(* Logix 5000 project; controller MyControlLogix vendor 1 type 14 code 51 rev 16.20; software revision 16.04 *)

TASK MainTask (continuous, watchdog 500 ms) : MainProgram

MODULES
   Local : vendor 1 type 14 code 51 (ICP 0, rev 16.20)
      AFC : vendor 1 type 0 code 15 (ICP 1, rev 1.1, Output RPI 5 ms)
END_MODULES

TYPE AFC :   // Main user defined data type
STRUCT
   Meters : AFC_Meters[16];   // Stores meter process variables, results, analysis (gas) and module profile
   MeterSignals : AFC_Meter_Reset;   // Sets meter signals (write archive, reset accumulator and select stream)
   ModbusGateway : AFC_Modbus;   // Reads and write data between processor and module modbus table
   ModbusMaster : AFC_ModbusMaster;   // Setup modbus master commands to be sent to remote slaves (through Port 3)
   ModbusPassThru : AFC_ModbusPassThru;   // Modbus pass-thru data
   Prove : AFC_Prove;   // Proving implementation (only firmware 2.07.000 or later)
   Flags : AFC_Flag;   // Wallclock update commands
   EnableMeter : AFC_Meter;   // Enable meters (this action can also be performed through AFC Manager)
   DisableMeter : AFC_Meter;   // Disable meters (this action can also be performed through AFC Manager)
   EnableStatus : AFC_Meter;   // Meter current status (0=disabled, 1=enabled)
   Site_Status : AFC_Site_Status;   // Site status
   Site_Alarms : AFC_Site_Alarms;   // Site Alarms
   CycleCounter : INT;   // Reflects current block ID calculated by ladder to be sent to the module
   inputbuffer : INT[250];   // Input buffer contains the complete block to be copied from the module
   outputbuffer : INT[248];   // Output buffer contains data the complete block to be copied to the module
   clockstructure : AFC_Time;   // Stores clock information
   Util : AFC_Util;   // Convenience variables used by ladder logic
END_STRUCT
END_TYPE

TYPE AFC_Analysis_High :   // High precision (floating point) Gas Analysis support. This feature is only supported for firmware version 2.07.000 or later
STRUCT
   EnableOnce : BOOL;   // Set to ON to request the high precision analysis update one time. It automatically resets to 0 after the request.
   Stream : INT;   // Stream number. Range is 0 (active) and 1 to 4.
   Components : AFC_Components_High;   // AFC High Precision Molar Analysis (floating point)
END_STRUCT
END_TYPE

TYPE AFC_Analysis_Low :   // Low precision (16-bit word) Gas Analysis support.
STRUCT
   EnableContinuous : BOOL;   // Set to ON to update the low precision molar analysis. The data will be updated continuously while the molar analysis is updated.
   Stream : INT;   // Select stream for molar analysis (low precision) update. Valid range is 0 (active) and 1 to 4.
   Components : AFC_Components_Low;   // Gas components in low precision format (16-bit word)
END_STRUCT
END_TYPE

TYPE AFC_Analysis_Status :   // Contains stream configuration information concerning high/low precision.
STRUCT
   Update : BOOL;   // Trigger update of analysis status
   Stream_Precision : SINT[4];   // Stream Precision ( 1 = Low, 2 = High)
   Slot_In_Stream : SINT[4];   // Slot number associated to each stream (0-BASED) Ex: (Slot_In_Stream[0] = 1 means stream 1 is set for slot 2)
   Slot_Precision : SINT[4];   // Precision of each slot (0-BASED) (2=high precision/first slot, 1=low precision,0=high precision/second slot)
END_STRUCT
END_TYPE

TYPE AFC_Components_High :   // High precision gas component analysis (only supported version 2.07.000)
STRUCT
   C1 : REAL;   // Methane
   N2 : REAL;   // Nitrogen
   CO2 : REAL;   // Carbon Dioxide
   C2 : REAL;   // Ethane
   C3 : REAL;   // Propane
   H20 : REAL;   // Water
   H2S : REAL;   // Hydrogen Sulphide
   H2 : REAL;   // Hydrogen
   CO : REAL;   // Carbon Monoxide
   O2 : REAL;   // Oxygen
   IC4 : REAL;   // Iso-butane
   NC4 : REAL;   // Normal Butane
   IC5 : REAL;   // Iso-pentane
   NC5 : REAL;   // Normal-pentane
   C6 : REAL;   // Hexane
   C7 : REAL;   // Heptane
   C8 : REAL;   // Octane
   C9 : REAL;   // Nonane
   C10 : REAL;   // Decane
   He : REAL;   // Helium
   Ar : REAL;   // Argon
   NeoC5 : REAL;   // Not Used
   Ux_User1 : REAL;   // Not Used
   Uy_User2 : REAL;   // Not Used
END_STRUCT
END_TYPE

TYPE AFC_Components_Low :   // Low precision gas component analysis
STRUCT
   C1 : INT;   // Methane
   N2 : INT;   // Nitrogen
   CO2 : INT;   // Carbon dioxide
   C2 : INT;   // Ethane
   C3 : INT;   // Propane
   H20 : INT;   // Water
   H2S : INT;   // Hydrogen sulphide
   H2 : INT;   // Hydrogen
   CO : INT;   // Carbon monoxide
   O2 : INT;   // Oxygen
   IC4 : INT;   // Iso-butane
   NC4 : INT;   // Normal butane
   IC5 : INT;   // Iso-pentane
   NC5 : INT;   // Normal pentane
   C6 : INT;   // Hexane
   C7 : INT;   // Heptane
   C8 : INT;   // Octane
   C9 : INT;   // Nonane
   C10 : INT;   // Decane
   He : INT;   // Helium
   Ar : INT;   // Argon
   NeoC5 : INT;   // Not used
   Ux_User1 : INT;   // Not used
   Uy_User2 : INT;   // Not used
END_STRUCT
END_TYPE

TYPE AFC_Flag :   // Flags contains status information updated by ladder and also trigger bits for clock update
STRUCT
   AFC_Stopped : BOOL;   // Indicates that the module has sent a new input block to be processed by ladder - UPDATED BY LADDER
   AFC_InputSequenceNum : INT;   // Meter number (0 -15) associated to blocks 1-16. Used to update "Profile" (meter type and product group.) UPDATED BY LADDER
   AFC_Set_Clock : BOOL;   // Set to 1 to update module wallclock (using processor as a source) UPDATED BY USER
   plc_set_clock : BOOL;   // Set to 1 to set processor wallclock UPDATED BY USER
END_STRUCT
END_TYPE

TYPE AFC_Meter :   // Used for meter enable and disable tags
STRUCT
   Meter1 : BOOL;   // Meter 1
   Meter2 : BOOL;   // Meter 2
   Meter3 : BOOL;   // Meter 3
   Meter4 : BOOL;   // Meter 4
   Meter5 : BOOL;   // Meter 5
   Meter6 : BOOL;   // Meter 6
   Meter7 : BOOL;   // Meter 7
   Meter8 : BOOL;   // Meter 8
   Meter9 : BOOL;   // Meter 9
   Meter10 : BOOL;   // Meter 10
   Meter11 : BOOL;   // Meter 11
   Meter12 : BOOL;   // Meter 12
   Meter13 : BOOL;   // Meter 13
   Meter14 : BOOL;   // Meter 14
   Meter15 : BOOL;   // Meter 15
   Meter16 : BOOL;   // Meter 16
END_STRUCT
END_TYPE

TYPE AFC_Meter_Analysis :   // Meter analysis components. Allows the processor to update molar analysis for low precision and high precision streams.
STRUCT
   Low_Precision : AFC_Analysis_Low;   // Low precision gas components (16-bit word per component)
   High_Precision : AFC_Analysis_High;   // High precision gas components (floating point per component). Only supported for firmware version 2.07.000 or later
   Status : AFC_Analysis_Status;   // Stream analysis status - contains stream and slot configuration data
END_STRUCT
END_TYPE

TYPE AFC_Meter_Differential_Gas_Input :   // Calculation results for differential meter with gas product
STRUCT
   Net_Accumulator : DINT;   // Net accumulator
   Net_Flowrate : REAL;   // Net flow rate
   Gross_Flowrate : REAL;   // Gross flow rate
   Fpv : REAL;   // Super compressibility
   Cprime : REAL;   // Cprime
END_STRUCT
END_TYPE

TYPE AFC_Meter_Differential_Gas_Output :   // Process Variables for differential meter with gas product
STRUCT
   Temperature : REAL;   // Temperature
   Pressure : REAL;   // Static pressure
   Differential_Pressure : REAL;   // Differential pressure if Primary Input = Differential pressure OR Flow Rate if Primary Input = Flow rate
END_STRUCT
END_TYPE

TYPE AFC_Meter_Differential_Liquid_Input :   // Calculation Results for differential meter with lliquid product
STRUCT
   Net_Accumulator : DINT;   // Net accumulator
   Net_Flowrate : REAL;   // Net flow rate
   Gross_Accumulator : DINT;   // Gross acumulator
   Gross_Standard_Accumulator : DINT;   // Gross standard accumulator
   Mass_Accumulator : DINT;   // Mass accumulator
END_STRUCT
END_TYPE

TYPE AFC_Meter_Differential_Liquid_Output :   // Process Variables for differential meter with liquid product
STRUCT
   Water_Percent : INT;   // Water %
   Temperature : REAL;   // Temperature
   Pressure : REAL;   // Static Pressure
   Differential_Pressure : REAL;   // Differential pressure if Primary Input = Differential pressure OR Flow Rate if Primary Input = Flow rate
   Density : REAL;   // Density
END_STRUCT
END_TYPE

TYPE AFC_Meter_Linear_Gas_Input :   // Calculation Results for linear meter with gas product
STRUCT
   Net_Accumulator : DINT;   // Net accumulator
   Net_Flowrate : REAL;   // Net flow rate
   Gross_Flowrate : REAL;   // Gross flow rate
   Fpv : REAL;   // Supercompressibility
   CPrime : REAL;   // CPrime
END_STRUCT
END_TYPE

TYPE AFC_Meter_Linear_Gas_Output :   // Process Variables for linear meter with gas product
STRUCT
   Temperature : REAL;   // Temperature
   Pressure : REAL;   // Pressure
   Meter_Pulses : DINT;   // Pulse count
   Pulse_Frequency : REAL;   // Pulse Frequency (Hz)
END_STRUCT
END_TYPE

TYPE AFC_Meter_Linear_Liquid_Input :   // Calculation Results for linear meter with liquid product
STRUCT
   Net_Accumulator : DINT;   // Net accumulator
   Net_Flowrate : REAL;   // Net flow rate
   Gross_Accumulator : DINT;   // Gross accumulator
   Gross_Standard_Accumulator : DINT;   // Gross standard accumulator
   Mass_Accumulator : DINT;   // Mass accumulator
END_STRUCT
END_TYPE

TYPE AFC_Meter_Linear_Liquid_Output :   // Process Variables for linear meter with liquid product
STRUCT
   Water_Percent : INT;   // Water (%)
   Temperature : REAL;   // Temperature
   Pressure : REAL;   // Pressure
   Meter_Pulses : DINT;   // Meter pulses
   Density : REAL;   // Density
   Pulse_Frequency : REAL;   // Pulse frequency (Hz)
END_STRUCT
END_TYPE

TYPE AFC_Meter_Reset :   // Meter signals to request for reset accumulator, select stream and write archives.
STRUCT
   Enable : BOOL;   // Enable meter signal request. UPDATED BY USER
   BID : INT;   // Block ID for meter signal request. UPDATED BY LOGIC
   Meter : INT;   // Meter number (1-16) associated to signal request UPDATED BY USER
   Action : INT;   // Action word built from Signal bits (UPDATED by USER)
   Signals : AFC_Meter_Signals;   // Signals request bits
   ResetOnce : BOOL;   // Request signal update once
   LastBlockID : INT;   // Last block ID associated to signals request
END_STRUCT
END_TYPE

TYPE AFC_Meter_Results :   // AFC meter results calculated by the module to the processor
STRUCT
   BID : INT;   // Block ID associated to calculation results
   Alarms : INT;   // Meter alarms
   DifferentialGas : AFC_Meter_Differential_Gas_Input;   // Differential meter / product gas
   DifferentialLiquid : AFC_Meter_Differential_Liquid_Input;   // Differential meter / product liquid
   LinearGas : AFC_Meter_Linear_Gas_Input;   // Linear meter / product gas
   LinearLiquid : AFC_Meter_Linear_Liquid_Input;   // Linear meter / product liquid
END_STRUCT
END_TYPE

TYPE AFC_Meter_Signals :   // Meter signals options
STRUCT
   Sel_Stream1 : BOOL;   // Set to 1 to select stream 1
   Sel_Stream2 : BOOL;   // Set to 1 to select stream 2
   Sel_Stream3 : BOOL;   // Set to 1 to select stream 3
   Sel_Stream4 : BOOL;   // Set to 1 to select stream 4
   Res_Acc1 : BOOL;   // Set to 1 to reset resettable accumulator 1
   Res_Acc2 : BOOL;   // Set to 1 to reset resettable accumulator 2
   Res_Acc3 : BOOL;   // Set to 1 to reset resettable accumulator 3
   Res_Acc4 : BOOL;   // Set to 1 to reset resettable accumulator 4
   Wr_Daily_Archive : BOOL;   // Set to 1 to write daily archive
   Wr_Hrly_Archive : BOOL;   // Set to 1 to write hourly archive
END_STRUCT
END_TYPE

TYPE AFC_Meter_Variables :   // Meter process variables from processor to the module.
STRUCT
   BID : INT;   // Block ID associated to meter process variable block (from processor to the module)
   DifferentialGas : AFC_Meter_Differential_Gas_Output;   // Differential meter and gas product
   DifferentialLiquid : AFC_Meter_Differential_Liquid_Output;   // Differential meter and liquid product
   LinearGas : AFC_Meter_Linear_Gas_Output;   // Linear meter and gas product
   LinearLiquid : AFC_Meter_Linear_Liquid_Output;   // Linear meter and liquid product
END_STRUCT
END_TYPE

TYPE AFC_Meters :   // Main meter data structure. Contains process variables, calculation results, gas analysis, profile update
STRUCT
   Variables : AFC_Meter_Variables;   // Input process variables to be transferred to the module
   Results : AFC_Meter_Results;   // Calculation results transferred from the module
   Analysis : AFC_Meter_Analysis;   // Molar Analysis data to be transferred to the module (only for gas products with online gas chromatograph applications)
   Profile : AFC_Status;   // Module profile (meter type/product group) transfered from the module
END_STRUCT
END_TYPE

TYPE AFC_Modbus :   // Modbus Gateway data structure. Select the number of commands to be used (1 to 10). O will disable this funcionality.
STRUCT
   CommandCount : INT;   // Defines the number of Modbus Gateway Blocks to be used (1 to 10). Set to 0 to disable the feature.
   Command : AFC_ModbusGateway[10];   // Modbus gateway commands - contains setup and modbus data
END_STRUCT
END_TYPE

TYPE AFC_ModbusConfig :   // Modbus gateway configuration options
STRUCT
   Enable : BOOL;   // Set to 1 to enable modbus gateway command (0=disable)
   StartRegister : INT;   // Start modbus address
   RegisterCount : INT;   // Word count (200 max)
   FunctionType_Write : BOOL;   // 0 = read command, 1 = write command
   RegisterType_Input : BOOL;   // 0 = holding register, 1 = input register
   SlaveType_Virtual : BOOL;   // 0 = primary slave, 1 = virtual slave
END_STRUCT
END_TYPE

TYPE AFC_ModbusGateway :   // Modbus gateway complete data structure
STRUCT
   Config : AFC_ModbusConfig;   // Config data to be entered by the user.
   BOD : INT;   // Block ID automatically generated by ladder
   WriteData : INT[200];   // Contains modbus data written to the module (write commands)
   BID : INT;   // Block ID automatically generated by ladder
   ReadData : INT[200];   // Contains modbus data read from the module (read commands)
END_STRUCT
END_TYPE

TYPE AFC_ModbusMaster :   // Modbus master operation. Port 3 must be configured as modbus master through AFC Manager to use this feature.
STRUCT
   Enable : BOOL;   // Enable the modbus master funcionality
   CommandIndex : INT;   // Selects which command index will be executed
   Command : AFC_ModbusMasterElement[10];   // Each command contains a specific modbus request to be sent out of the port
END_STRUCT
END_TYPE

TYPE AFC_ModbusMasterConfig :   // Modbus master command settings
STRUCT
   Enable : BOOL;   // Set to 1 to enable command (0=disable)
   FunctionType_Write : BOOL;   // Set to 1 to select write command (0=read command)
   RegisterBank_Input : BOOL;   // Set to 1 to select input register (0=holding register)
   DataType : AFC_ModbusMasterDataType;   // Select data type format
   SwapOption : AFC_ModbusMasterSwap;   // Select byte and word swap (1 = swap, 0 = no swap)
   Type_Swap : INT;   // This value is calculated by ladder logic and must not be modified by user
   SlaveAddress : INT;   // Modbus slave address of remote device
   ModbusAddress : INT;   // Modbus data address on remote slave
   ElementCount : INT;   // Number of data elements (125 words)
END_STRUCT
END_TYPE

TYPE AFC_ModbusMasterDataType :   // Modbus master data type selection
STRUCT
   Bit : BOOL;   // bit type
   Word : BOOL;   // word type (16-bit)
   Long : BOOL;   // long integer (32-bit)
   LongRemote : BOOL;   // long integer (32-bit)
END_STRUCT
END_TYPE

TYPE AFC_ModbusMasterElement :   // Modbus master controller tag. Requires port 3 to be configured as a modbus master device.
STRUCT
   Output : AFC_ModbusMasterOut;   // From processor to the module
   Input : AFC_ModbusMasterIn;   // From module to the processor
END_STRUCT
END_TYPE

TYPE AFC_ModbusMasterIn :   // Modbus master input tag.
STRUCT
   BID : INT;   // Block id associated to modbus master request
   TransactionNumber : INT;   // Transaction number associated to modbus command index
   ErrorCode : INT;   // Error code associated to modbus master command
   Pending : BOOL;   // Pending modbus master command - waiting for modbus response
   ReadData : INT[100];   // Data read fro mremote slave device
END_STRUCT
END_TYPE

TYPE AFC_ModbusMasterOut :   // Modbus master request from processor to the module
STRUCT
   Config : AFC_ModbusMasterConfig;   // Modbus master command configuration settings
   TransactionNumber : INT;   // Transaction number used to keep track of diffeernt commands (echoed back in response)
   BOD : INT;   // Block output ID
   WriteData : INT[100];   // Write data associated to the write command
END_STRUCT
END_TYPE

TYPE AFC_ModbusMasterSwap :   // Modbus master swap words/ swap bytes
STRUCT
   Swap_Words : BOOL;   // Swap words
   Swap_Bytes : BOOL;   // Swap bytes
END_STRUCT
END_TYPE

TYPE AFC_ModbusPassThru :   // AFC modbus pass through controller tag
STRUCT
   Output : AFC_ModbusPassThruOut;   // Values to be transferred from processor to the module
   Input : AFC_ModbusPassThruIn;   // Values to be transferred from module to processor
END_STRUCT
END_TYPE

TYPE AFC_ModbusPassThruIn :   // Modbus pass through input
STRUCT
   BID : INT;   // Calculated by ladder logic
   MessagePresent : BOOL;   // Message present in the response block
   Function_BitWrite : BOOL;   // Function bit write
   OverflowError : BOOL;   // Overflow error flag
   ModbusAddress : INT;   // Destination modbus address
   RegisterCount : INT;   // Number of elements associated to command
   ReadData_Word : INT[125];   // Contains received data for word commands
   ReadData_Bit : BOOL[2016];   // Contains received data for bit commands
END_STRUCT
END_TYPE

TYPE AFC_ModbusPassThruOut :   // AFC Modbus pass through output block fro mprocessor to the module
STRUCT
   BOD : INT;   // Automatically calculated by sample ladder
   Enable : BOOL;   // Set to 1 to enable pass-thru funcionality (requires AFC Manager setting)
END_STRUCT
END_TYPE

TYPE AFC_Prove :   // Implements prove funcionality. Supported only for firmware version 2.07 or later.
STRUCT
   Output : AFC_Prove_Output;   // Prover output block to the module
   Input : AFC_Prove_Input;   // Prover input block from the module
END_STRUCT
END_TYPE

TYPE AFC_Prove_Config :   // Controls (configuration settings) associated to the prover
STRUCT
   Enable : AFC_Prove_Config_Enable;   // Controls at enable
   Accept : AFC_Prove_Config_Accept;   // Controls at accept
END_STRUCT
END_TYPE

TYPE AFC_Prove_Config_Accept :   // Prove controls at accept. If auto-accept is selected must be available at enable
STRUCT
   Requested_Interpolation_Point : INT;   // Requested interpolation point (0 nearest)
   Apply_MF_Change_All_Streams : BOOL;   // Apply change in meter factor to all streams
   Apply_MF_Change_Curve : BOOL;   // Apply change in meter factor to all curve points
   Apply_New_MF : BOOL;   // CApply new meter factor
END_STRUCT
END_TYPE

TYPE AFC_Prove_Config_Enable :   // Prove controls at enable
STRUCT
   Meter_Number : INT;   // Meter number requested (1-16)
   Auto_Accept_Prove : BOOL;   // Auto-accept the prove
   Auto_Continue_Prove : BOOL;   // Auto-continue the prove
END_STRUCT
END_TYPE

TYPE AFC_Prove_Input :   // AFC Prove input block
STRUCT
   Config : AFC_Prove_Input_Config;   // AFC prover input configuration
   Status : AFC_Prove_Status;   // AFC prover status
   Error_Code : INT;   // Prove error code
   Prove_controls_Echo : INT;   // AFC module Echos the state of the Prove Controls
   Requested_Meter_Echo : INT;   // AFC module Echos the Meter number requested
   Requested_Curve_Point_Echo : INT;   // AFC module Echos the requested Curve Point
   Run_Results : AFC_Prove_Run_Results;   // Prove and run results
   Prove_Enabled : BOOL;   // ON if prove is enabled. This flag is coped from inputbuffer[247]
END_STRUCT
END_TYPE

TYPE AFC_Prove_Input_Config :   // Prove input block results - prover configuration
STRUCT
   Type : INT;   // Prover type
   Options : INT;   // Prover options
   Runs_Per_Prove_Total : INT;   // Total runs per prove
   Runs_Per_Prove_Selected : INT;   // Selected runs per prove
   Max_Runs_before_Abort : INT;   // Max total runs before abort
   Short_Passes_Per_Run : INT;   // Short passes per run if bidir = 2 , else 0
END_STRUCT
END_TYPE

TYPE AFC_Prove_Output :   // AFC Prove output block
STRUCT
   Process : AFC_Prove_Process;   // Process Variables
   Signals : AFC_Prove_Signals;   // AFC Prove Signals (triggers the proving update)
   Config : AFC_Prove_Config;   // AFC Prove Control (configuration settings)
   Pulse_Counts : AFC_Prove_Pulse_Count;   // Pulse counts to be updated at the end of the run/pass
END_STRUCT
END_TYPE

TYPE AFC_Prove_Phase_Bitmap :   // AFC prove phase bitmap
STRUCT
   Not_Selected : BOOL;   // Not selected
   Active : BOOL;   // Active, not counting
   Counting_Past_1st_Switch : BOOL;   // Counting past 1st switch for Udir and forward leg for Bdir)
   Past_2nd_Switch_Fwd_Leg : BOOL;   // Past 2nd switch forward leg (bidirectional only)
   Past_1st_Swith_Ret_Leg : BOOL;   // Past 1st switch return leg (bidirectional only)
   Run_Complete : BOOL;   // Run complete. past 2nd switch.
END_STRUCT
END_TYPE

TYPE AFC_Prove_Process :   // Prove process output from processor to the module
STRUCT
   Sequencing : AFC_Prove_Sequencing;   // Prover sequencing
   Temperature : REAL;   // Temperature for Single Probe provers. And Inlet Temperature for Dual Probe Provers.
   Outlet_Temperature : REAL;   // Outlet Temperature for Provers with Dual Probes.
   Switch_Bar_Temperature : REAL;   // Switch bar temperature
   Pressure : REAL;   // Pressure for Single Probe provers. And Inlet Pressure for Dual Probe Provers.
   Outlet_Pressure : REAL;   // Outlet Pressure for Provers with Dual Probes.
   Prover_Density : REAL;   // Prover density
END_STRUCT
END_TYPE

TYPE AFC_Prove_Pulse_Count :   // Values to be supplied at the end of the pass/run
STRUCT
   Meter : DINT;   // Meter pulse count
   Master_Meter : DINT;   // Master meter pulse count
END_STRUCT
END_TYPE

TYPE AFC_Prove_Run_Results :   // Run results of the prove. Copied from the module to the pocessor
STRUCT
   Count_Attempted : INT;   // Run count attempted
   Count_Completed : INT;   // Run count completed
   Count_Selected : INT;   // Run count selected
   Runs_Selected : INT;   // Bit Mapped Runs selected for calculations from completed runs
   New_Meter_Factor : REAL;   // New meter factor
   Change_In_Meter_Factor : REAL;   // Change in meter factor
END_STRUCT
END_TYPE

TYPE AFC_Prove_Sequencing :   // AFC prove sequencing tag for phase selection and ball positioning
STRUCT
   Phase : AFC_Prove_Phase_Bitmap;   // AFC phase sequencing
   Ball_Position_Ready : BOOL;   // Ball position: Ready (Udir & Bdir only; fwd leg Bdir)
   Ball_Position_Sealed : BOOL;   // Ball position: Sealed (Udir & Bdir only; fwd leg Bdir)
   Ball_Position_Ready_Bwd_Leg : BOOL;   // Ball position: Ready bwd leg (Bdir only)
   Ball_Position_Sealed_Bwd_Leg : BOOL;   // Ball position: Sealed bwd leg (Bdir only)
END_STRUCT
END_TYPE

TYPE AFC_Prove_Signals :   // Contains the proving signals that will trigger specific tasks from the module
STRUCT
   EnableProve : BOOL;   // Enables the prove
   AcceptProve : BOOL;   // Accepts the prove
   RejectProve : BOOL;   // Reject the prove
   RunStart : BOOL;   // Starts the run
   RunComplete : BOOL;   // Flags that the run is complete
   RunCancel : BOOL;   // Cancels the run
   RunDelete : BOOL;   // Deletes the run
   PassComplete : BOOL;   // Flag that the pass is complete
   PauseProve : BOOL;   // Pauses the Proving Process
   AbortProve : BOOL;   // Aborts the prove
END_STRUCT
END_TYPE

TYPE AFC_Prove_Status :   // Status of the prove (returned from the module to the processor)
STRUCT
   Prove_Accepted : BOOL;   // Prove was accepted
   Meter_Factor_Applied : BOOL;   // Meter factor was applied
   MF_Applied_To_Curve : BOOL;   // Meter factor was applied to all points in the curve
   MF_Applied_To_Streams : BOOL;   // Meter factor was applied to all streams
   Prove_Rejected_By_Command : BOOL;   // Prove was rejected by command
   Prove_Rejected_No_Runs : BOOL;   // Prove was rejected - empty prove (no runs)
   Prove_Rejected_Divide_By_0 : BOOL;   // Prove was rejected - divide by 0
   Prove_Enabled : BOOL;   // Prove is enabled
   Proving_Run_In_Progress : BOOL;   // Proving run is in progress
   Prove_Rejected_Abort : BOOL;   // Prove rejected: abort
   Prove_Paused : BOOL;   // Prove is paused
   Run_Cancelled : BOOL;   // Run Is cancelled
   Run_Timed_Out : BOOL;   // Run timed out
END_STRUCT
END_TYPE

TYPE AFC_Site_Alarms :   // Indicates if a meter has any alarms
STRUCT
   Meter1 : BOOL;   // Meter in alarm
   Meter2 : BOOL;   // Meter in alarm
   Meter3 : BOOL;   // Meter in alarm
   Meter4 : BOOL;   // Meter in alarm
   Meter5 : BOOL;   // Meter in alarm
   Meter6 : BOOL;   // Meter in alarm
   Meter7 : BOOL;   // Meter in alarm
   Meter8 : BOOL;   // Meter in alarm
   Meter9 : BOOL;   // Meter in alarm
   Meter10 : BOOL;   // Meter in alarm
   Meter11 : BOOL;   // Meter in alarm
   Meter12 : BOOL;   // Meter in alarm
   Meter13 : BOOL;   // Meter in alarm
   Meter14 : BOOL;   // Meter in alarm
   Meter15 : BOOL;   // Meter in alarm
   Meter16 : BOOL;   // Meter in alarm
END_STRUCT
END_TYPE

TYPE AFC_Site_Status :   // Site status bits - contains general information about the module - not meter specific
STRUCT
   AFC_ACTIVE : BOOL;   // AFC active
   Checksum_Alarms : BOOL;   // Checkum alarm active
   reserved2 : BOOL;
   reserved3 : BOOL;
   PLC_HALTED : BOOL;   // PLC in program mode or missing
   Cfg_changed : BOOL;   // Configuration changed
   Powerup : BOOL;   // Module powered up
   ColdStart : BOOL;   // Module performed cold start (BBRAM initialized)
   HardPassword : BOOL;   // Hard password selected
   reserved9 : BOOL;
   reserved10 : BOOL;
   reserved11 : BOOL;
   reserved12 : BOOL;
   reserved13 : BOOL;
   reserved14 : BOOL;
   reserved15 : BOOL;
END_STRUCT
END_TYPE

TYPE AFC_Status :   // General meter configuration profile
STRUCT
   MeterType : BOOL;   // 0=Differential, 1=Linear
   ProductGroup : BOOL;   // 0=Gas, 1=Liquid
   SelectedStream : INT;   // Selected Stream (1 through 4). Only supported for firmware version 2.05.000 or later
END_STRUCT
END_TYPE

TYPE AFC_Time :   // AFC time format used for walclock update
STRUCT
   Year : DINT;   // Year
   Month : DINT;   // Month
   Day : DINT;   // Day
   Hour : DINT;   // Hour
   Minute : DINT;   // Minute
   second : DINT;   // Seconds
   msec : DINT;   // Milliseconds
END_STRUCT
END_TYPE

TYPE AFC_Util :   // Used for internal ladder logic usage. These values must not be changed by user application.
STRUCT
   MeterIndex1 : INT;   // Meter index for process variable calculation
   Offset1 : INT;   // Offset for meter process calculation
   MeterIndex2 : INT;   // Meter index for calculation results
   Offset2 : INT;   // Offset for calculation results
   SignalsTimer : TIMER;   // Signals timer
   IndexOut : INT;   // Index output
   IndexIn : INT;   // Index input
   CycleCounterRollover : INT;   // Rollover value for cycle counter for block ID calculation
   LongCount : INT;   // Long count for modbus master command
   LastRegularBlockID : INT;   // Rollover block ID
   Current_meter : SINT;   // Current meter number analysis update
   MaskedStream : INT;   // Masked stream
   AnalysisMeterNumber : INT;   // Analysis meter number
   AnalysisBID : INT;   // Analysis block ID
   AnalysisStreamMasked : INT;   // Analysis stream masked information
   v206orLater : INT;   // indicates if the meter is 2.06 or later so the module supports high precision analysis
   AnalysisHighPrecisionBOD : INT;   // Analysis high precision number
   Firmware_Version : SINT[2];   // Firmware version number
   Firmware_Revision : INT;   // firmware revision number
   AnalysisHMeter : INT;   // Meter associated to molar high precision
   SlotPrecision : SINT[4];   // Slot precision number for stream precision calculation
   SlotInStream : DINT[4];   // Slot number for stream X
   PowerUp_HighAnalysis : BOOL;   // Request high analysis block upon power up
   Meter_HighAnalysis : INT;   // Meter number for high precision analysis
   TempSlotInStream : SINT;   // Used to calculate stream precision based on slot precision
   AnalysisHighPrecisionBID : INT[16];   // High precision block ID
   AnalysisHighPrecisionBID_Update : INT;   // molar block id update
   Reinitialize_Timer : TIMER;   // Timer to initialize block ID if freezes
   Prover_Phase : INT;   // Prover phase integer word to assemble all bits
   Prover_Signals : INT;   // Prover signals integer word to assemble all bits
   Prover_Controls : INT;   // Prover control word to assemble all bits
END_STRUCT
END_TYPE

ADD_ON_INSTRUCTION AOI56AFC   (* revision 1.3, ExecutePrescan *)
// MVI56-AFC Add-On Instruction
// Revision note:
// - Supports proving and high analysis (v2.07.000)
// - Fixes minor fault to CLX
// - Copies CPrime for Linear/Gas meter
// Help:
// v1.3 Update Modbus Gateway Read Function.
VAR_IN_OUT
   Connection_Input : INT[250]; {required}
   Connection_Output : INT[248]; {required}
   AFC56 : AFC; {required}
END_VAR
VAR
   MJFAULTS : DINT[12];
END_VAR

ROUTINE Logic   (* ladder *)
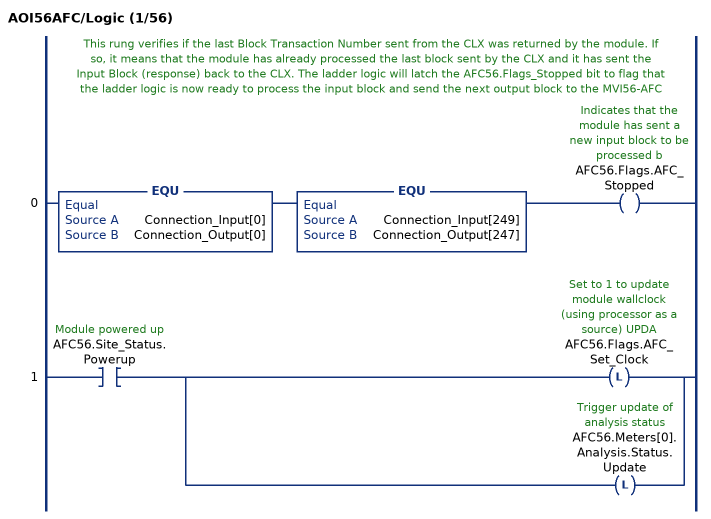
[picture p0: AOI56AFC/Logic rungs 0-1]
   // This rung verifies if the last Block Transaction Number sent from the CLX was returned by the module. If so, it means that the module has already processed the last block sent by the CLX and it has sent the Input Block (response) back to the CLX. The ladder logic will latch the AFC56.Flags_Stopped bit to flag that the ladder logic is now ready to process the input block and send the next output block to the MVI56-AFC
   0: EQU(Connection_Input[0],Connection_Output[0])EQU(Connection_Input[249],Connection_Output[247])OTE(AFC56.Flags.AFC_Stopped);
   1: XIC(AFC56.Site_Status.Powerup)[OTL(AFC56.Flags.AFC_Set_Clock) ,OTL(AFC56.Meters[0].Analysis.Status.Update) ];
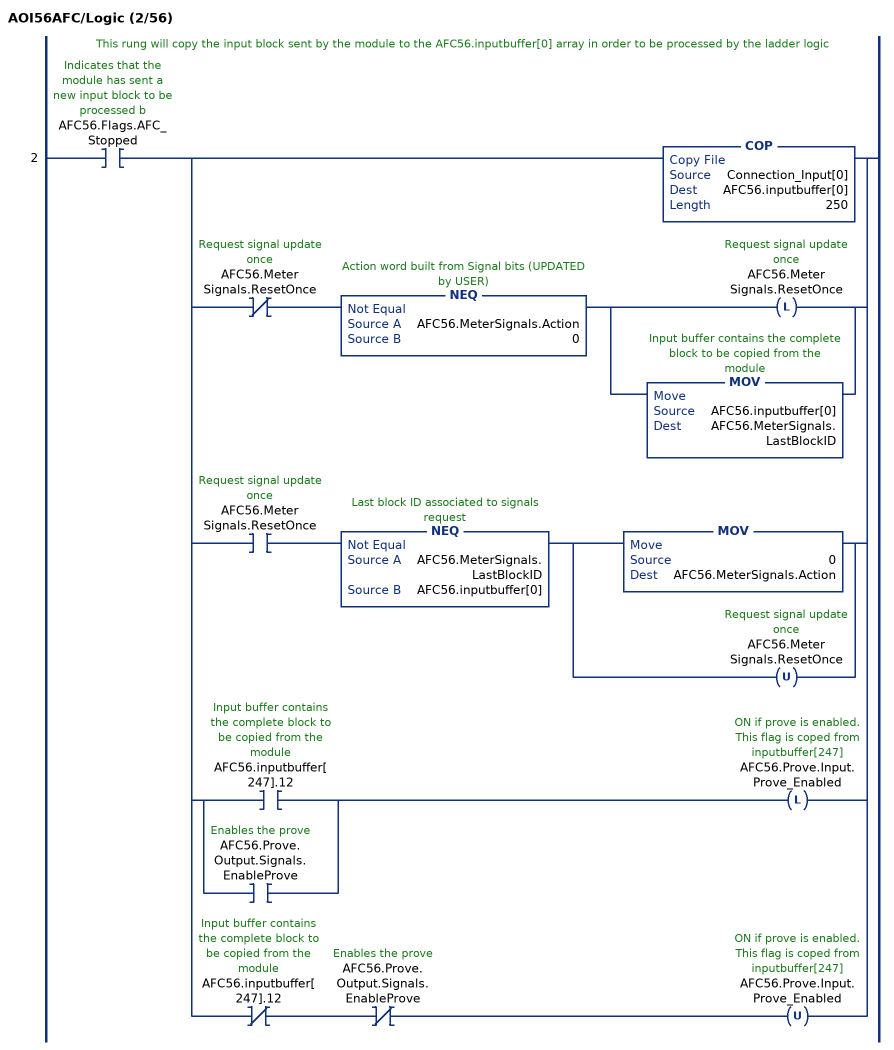
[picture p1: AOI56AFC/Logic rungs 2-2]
   // This rung will copy the input block sent by the module to the AFC56.inputbuffer[0] array in order to be processed by the ladder logic
   2: XIC(AFC56.Flags.AFC_Stopped)[COP(Connection_Input[0],AFC56.inputbuffer[0],250) ,XIO(AFC56.MeterSignals.ResetOnce) NEQ(AFC56.MeterSignals.Action,0) [OTL(AFC56.MeterSignals.ResetOnce) ,MOV(AFC56.inputbuffer[0],AFC56.MeterSignals.LastBlockID) ] ,XIC(AFC56.MeterSignals.ResetOnce) NEQ(AFC56.MeterSignals.LastBlockID,AFC56.inputbuffer[0]) [MOV(0,AFC56.MeterSignals.Action) ,OTU(AFC56.MeterSignals.ResetOnce) ] ,[XIC(AFC56.inputbuffer[247].12) ,XIC(AFC56.Prove.Output.Signals.EnableProve) ] OTL(AFC56.Prove.Input.Prove_Enabled) ,XIO(AFC56.inputbuffer[247].12) XIO(AFC56.Prove.Output.Signals.EnableProve) OTU(AFC56.Prove.Input.Prove_Enabled) ];
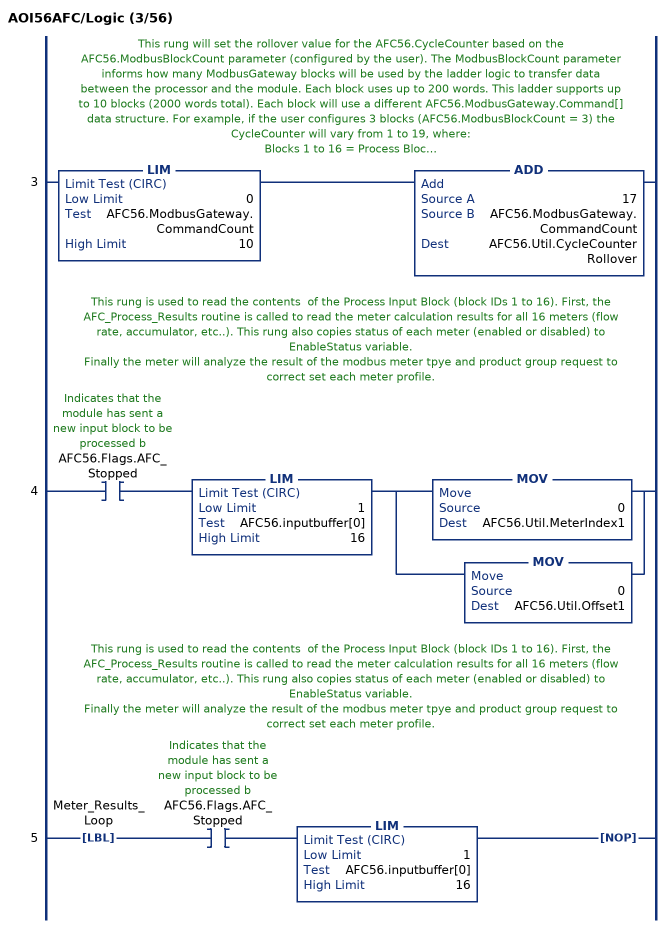
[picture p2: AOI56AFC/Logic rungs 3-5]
   // This rung will set the rollover value for the AFC56.CycleCounter based on the AFC56.ModbusBlockCount parameter (configured by the user). The ModbusBlockCount parameter informs how many ModbusGateway blocks will be used by the ladder logic to transfer data
   // between the processor and the module. Each block uses up to 200 words. This ladder supports up to 10 blocks (2000 words total). Each block will use a different AFC56.ModbusGateway.Command[] data structure. For example, if the user configures 3 blocks (AFC56.ModbusBlockCount = 3) the CycleCounter will vary from 1 to 19, where:
   // Blocks 1 to 16 = Process Block
   // Block 17 = Modbus Gateway Block 1 (uses AFC56.ModbusGateway.Command[0])
   // Block 18 = Modbus Gateway Block 2 (uses AFC56.ModbusGateway.Command[1])
   // Block 19 = Modbus Gateway Block 3 (uses AFC56.ModbusGateway.Command[2])
   3: LIM(0,AFC56.ModbusGateway.CommandCount,10)ADD(17,AFC56.ModbusGateway.CommandCount,AFC56.Util.CycleCounterRollover);
   // This rung is used to read the contents  of the Process Input Block (block IDs 1 to 16). First, the AFC_Process_Results routine is called to read the meter calculation results for all 16 meters (flow rate, accumulator, etc..). This rung also copies status of each meter (enabled or disabled) to EnableStatus variable.
   // Finally the meter will analyze the result of the modbus meter tpye and product group request to correct set each meter profile.
   4: XIC(AFC56.Flags.AFC_Stopped)LIM(1,AFC56.inputbuffer[0],16)[MOV(0,AFC56.Util.MeterIndex1) ,MOV(0,AFC56.Util.Offset1) ];
   // This rung is used to read the contents  of the Process Input Block (block IDs 1 to 16). First, the AFC_Process_Results routine is called to read the meter calculation results for all 16 meters (flow rate, accumulator, etc..). This rung also copies status of each meter (enabled or disabled) to EnableStatus variable.
   // Finally the meter will analyze the result of the modbus meter tpye and product group request to correct set each meter profile.
   5: LBL(Meter_Results_Loop)XIC(AFC56.Flags.AFC_Stopped)LIM(1,AFC56.inputbuffer[0],16)NOP();
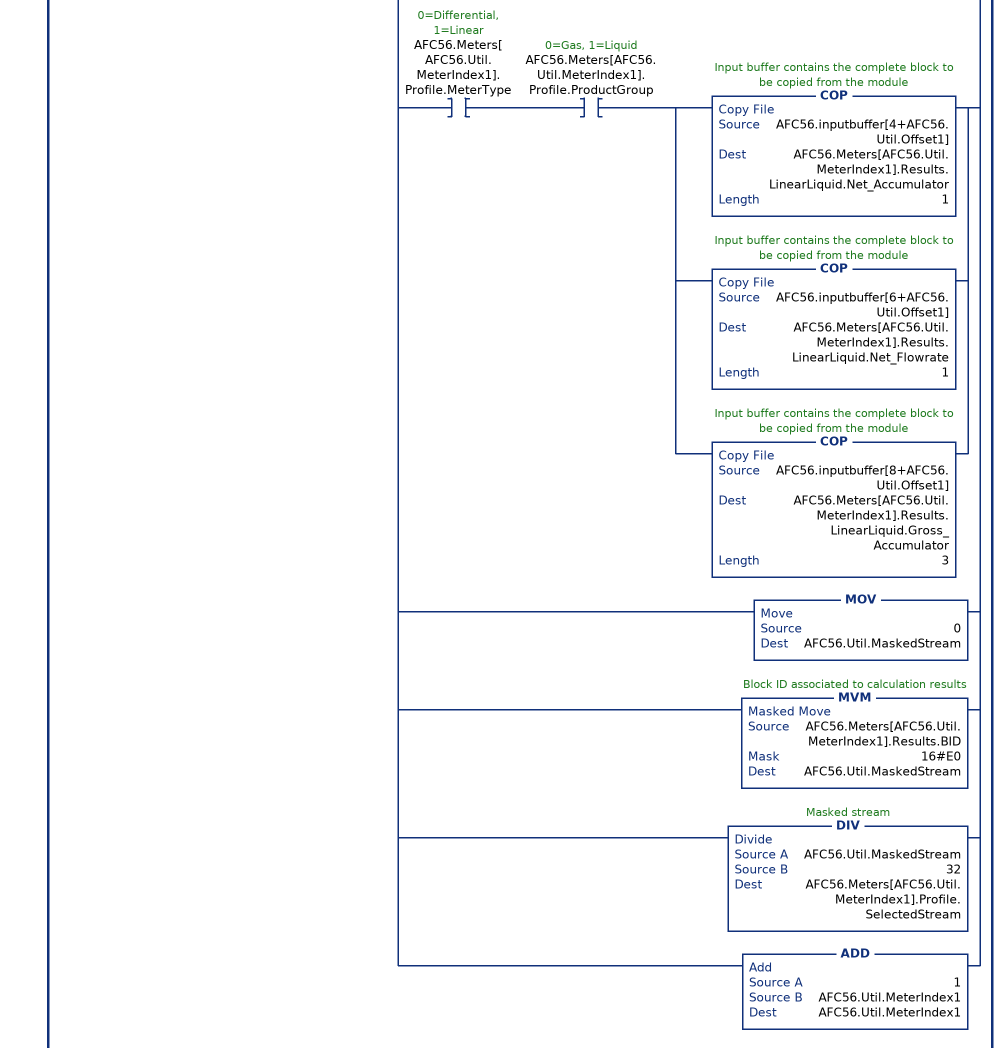
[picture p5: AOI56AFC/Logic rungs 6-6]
   // This rung is used to read the contents  of the Process Input Block (block IDs 1 to 16). First, the AFC_Process_Results routine is called to read the meter calculation results for all 16 meters (flow rate, accumulator, etc..). This rung also copies status of each meter (enabled or disabled) to EnableStatus variable.
   // Finally the meter will analyze the result of the modbus meter tpye and product group request to correct set each meter profile.
   6: XIC(AFC56.Flags.AFC_Stopped)LIM(1,AFC56.inputbuffer[0],16)[CPT(AFC56.Util.Offset1,AFC56.Util.MeterIndex1*12) ,MOV(AFC56.inputbuffer[2+AFC56.Util.Offset1],AFC56.Meters[AFC56.Util.MeterIndex1].Results.BID) ,MOV(AFC56.inputbuffer[3+AFC56.Util.Offset1],AFC56.Meters[AFC56.Util.MeterIndex1].Results.Alarms) ,XIO(AFC56.Meters[AFC56.Util.MeterIndex1].Profile.MeterType) XIO(AFC56.Meters[AFC56.Util.MeterIndex1].Profile.ProductGroup) [COP(AFC56.inputbuffer[4+AFC56.Util.Offset1],AFC56.Meters[AFC56.Util.MeterIndex1].Results.DifferentialGas.Net_Accumulator,1) ,COP(AFC56.inputbuffer[6+AFC56.Util.Offset1],AFC56.Meters[AFC56.Util.MeterIndex1].Results.DifferentialGas.Net_Flowrate,4) ] ,XIO(AFC56.Meters[AFC56.Util.MeterIndex1].Profile.MeterType) XIC(AFC56.Meters[AFC56.Util.MeterIndex1].Profile.ProductGroup) [COP(AFC56.inputbuffer[4+AFC56.Util.Offset1],AFC56.Meters[AFC56.Util.MeterIndex1].Results.DifferentialLiquid.Net_Accumulator,1) ,COP(AFC56.inputbuffer[6+AFC56.Util.Offset1],AFC56.Meters[AFC56.Util.MeterIndex1].Results.DifferentialLiquid.Net_Flowrate,1) ,COP(AFC56.inputbuffer[8+AFC56.Util.Offset1],AFC56.Meters[AFC56.Util.MeterIndex1].Results.DifferentialLiquid.Gross_Accumulator,3) ] ,XIC(AFC56.Meters[AFC56.Util.MeterIndex1].Profile.MeterType) XIO(AFC56.Meters[AFC56.Util.MeterIndex1].Profile.ProductGroup) [COP(AFC56.inputbuffer[4+AFC56.Util.Offset1],AFC56.Meters[AFC56.Util.MeterIndex1].Results.LinearGas.Net_Accumulator,1) ,COP(AFC56.inputbuffer[6+AFC56.Util.Offset1],AFC56.Meters[AFC56.Util.MeterIndex1].Results.LinearGas.Net_Flowrate,4) ] ,XIC(AFC56.Meters[AFC56.Util.MeterIndex1].Profile.MeterType) XIC(AFC56.Meters[AFC56.Util.MeterIndex1].Profile.ProductGroup) [COP(AFC56.inputbuffer[4+AFC56.Util.Offset1],AFC56.Meters[AFC56.Util.MeterIndex1].Results.LinearLiquid.Net_Accumulator,1) ,COP(AFC56.inputbuffer[6+AFC56.Util.Offset1],AFC56.Meters[AFC56.Util.MeterIndex1].Results.LinearLiquid.Net_Flowrate,1) ,COP(AFC56.inputbuffer[8+AFC56.Util.Offset1],AFC56.Meters[AFC56.Util.MeterIndex1].Results.LinearLiquid.Gross_Accumulator,3) ] ,[MOV(0,AFC56.Util.MaskedStream) ,MVM(AFC56.Meters[AFC56.Util.MeterIndex1].Results.BID,16#E0,AFC56.Util.MaskedStream) ,DIV(AFC56.Util.MaskedStream,32,AFC56.Meters[AFC56.Util.MeterIndex1].Profile.SelectedStream) ] ,ADD(1,AFC56.Util.MeterIndex1,AFC56.Util.MeterIndex1) ];
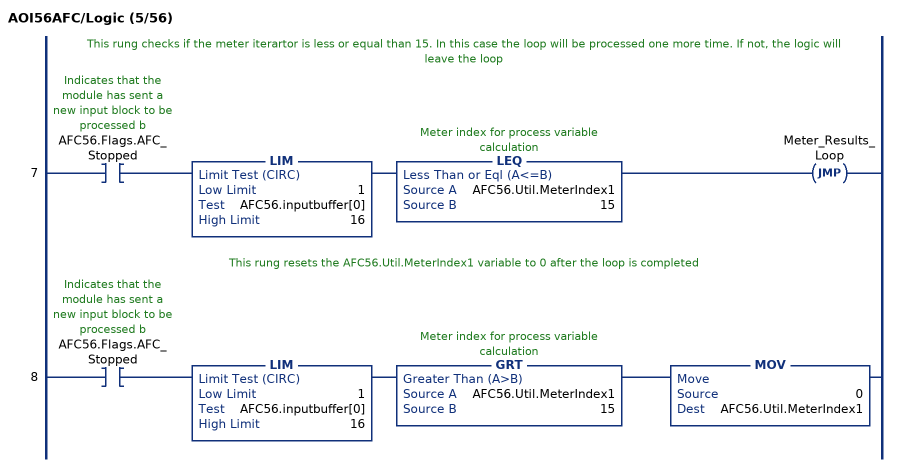
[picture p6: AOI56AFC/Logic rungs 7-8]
   // This rung checks if the meter iterartor is less or equal than 15. In this case the loop will be processed one more time. If not, the logic will leave the loop
   7: XIC(AFC56.Flags.AFC_Stopped)LIM(1,AFC56.inputbuffer[0],16)LEQ(AFC56.Util.MeterIndex1,15)JMP(Meter_Results_Loop);
   // This rung resets the AFC56.Util.MeterIndex1 variable to 0 after the loop is completed
   8: XIC(AFC56.Flags.AFC_Stopped)LIM(1,AFC56.inputbuffer[0],16)GRT(AFC56.Util.MeterIndex1,15)MOV(0,AFC56.Util.MeterIndex1);
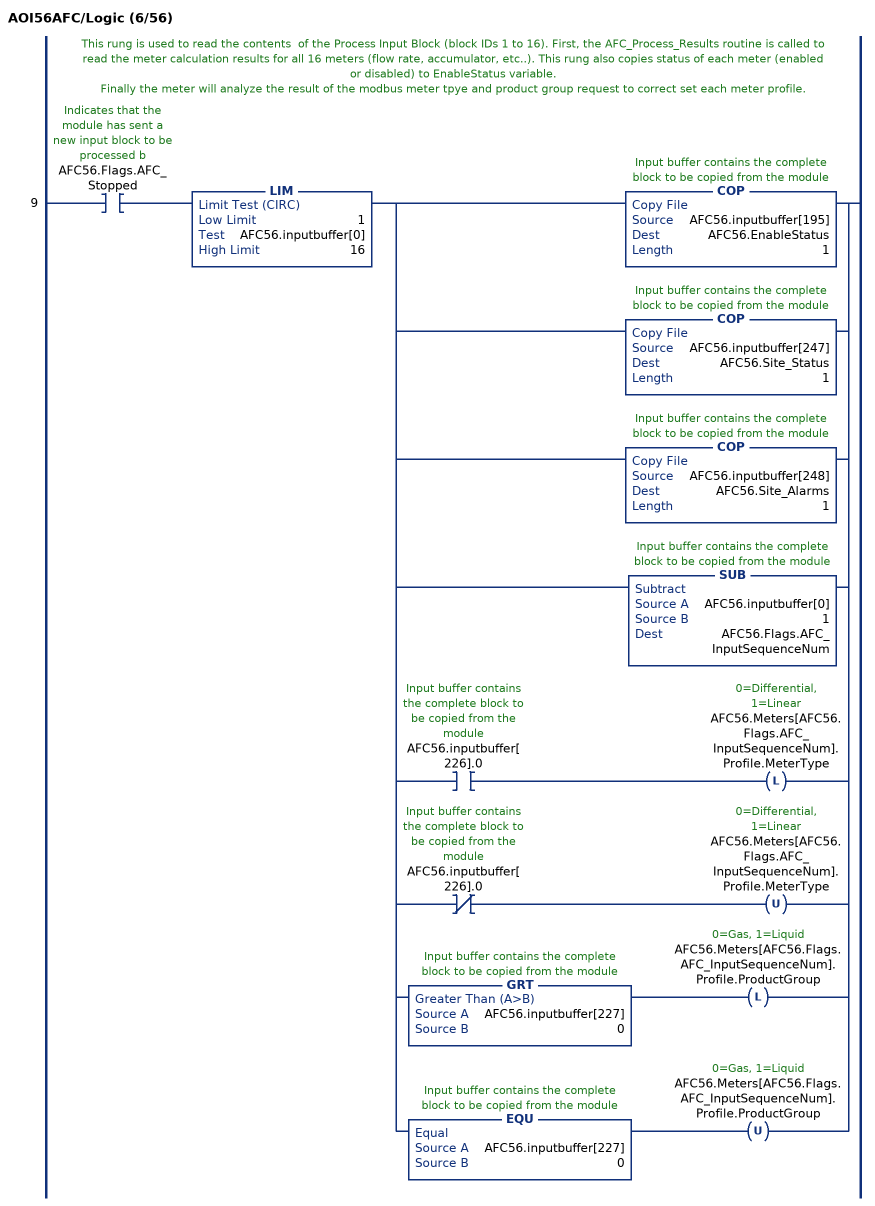
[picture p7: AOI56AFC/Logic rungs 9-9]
   // This rung is used to read the contents  of the Process Input Block (block IDs 1 to 16). First, the AFC_Process_Results routine is called to read the meter calculation results for all 16 meters (flow rate, accumulator, etc..). This rung also copies status of each meter (enabled or disabled) to EnableStatus variable.
   // Finally the meter will analyze the result of the modbus meter tpye and product group request to correct set each meter profile.
   9: XIC(AFC56.Flags.AFC_Stopped)LIM(1,AFC56.inputbuffer[0],16)[COP(AFC56.inputbuffer[195],AFC56.EnableStatus,1) ,COP(AFC56.inputbuffer[247],AFC56.Site_Status,1) ,COP(AFC56.inputbuffer[248],AFC56.Site_Alarms,1) ,SUB(AFC56.inputbuffer[0],1,AFC56.Flags.AFC_InputSequenceNum) ,XIC(AFC56.inputbuffer[226].0) OTL(AFC56.Meters[AFC56.Flags.AFC_InputSequenceNum].Profile.MeterType) ,XIO(AFC56.inputbuffer[226].0) OTU(AFC56.Meters[AFC56.Flags.AFC_InputSequenceNum].Profile.MeterType) ,GRT(AFC56.inputbuffer[227],0) OTL(AFC56.Meters[AFC56.Flags.AFC_InputSequenceNum].Profile.ProductGroup) ,EQU(AFC56.inputbuffer[227],0) OTU(AFC56.Meters[AFC56.Flags.AFC_InputSequenceNum].Profile.ProductGroup) ];
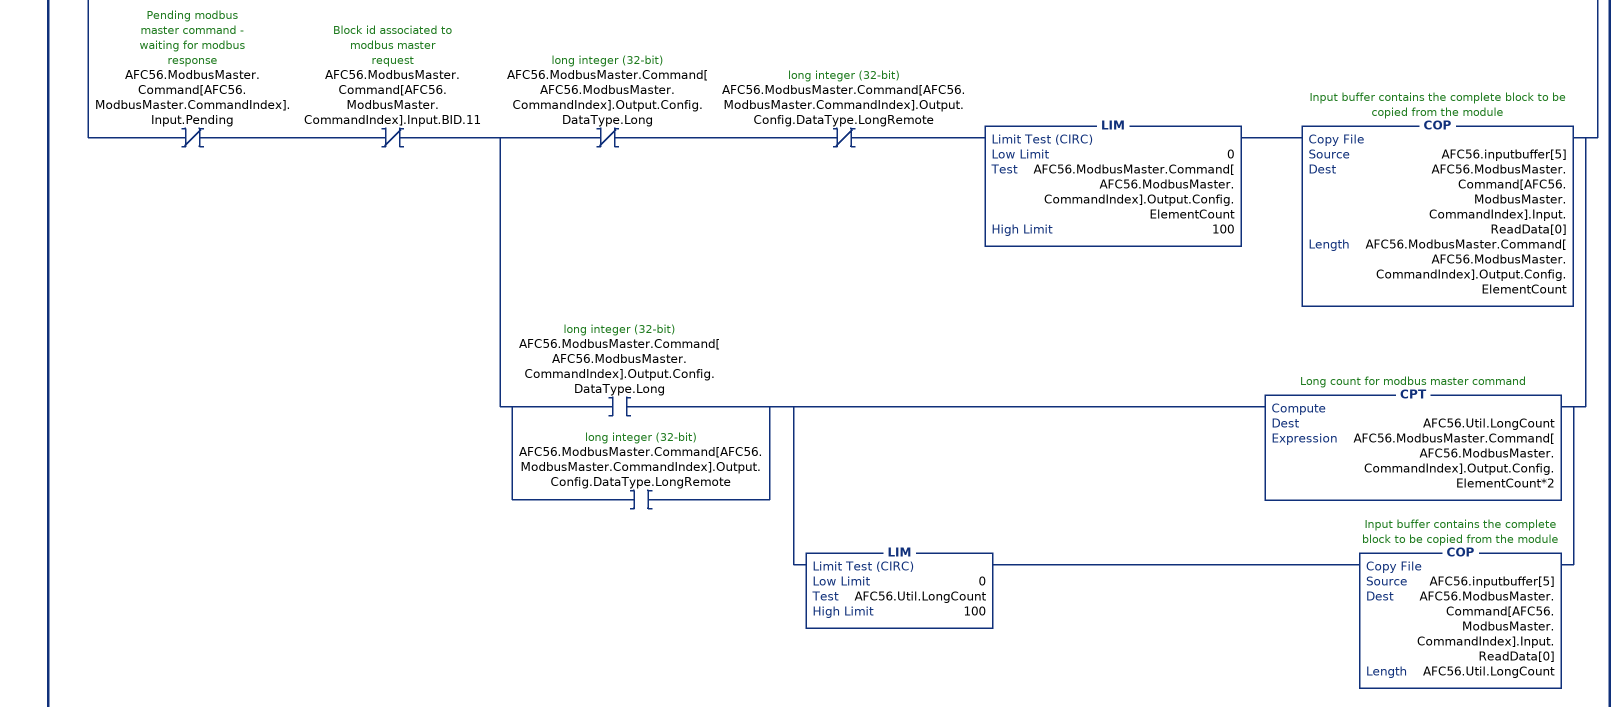
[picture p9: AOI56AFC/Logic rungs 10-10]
   // This rung is used to read the contents  of the Process Input Block (block IDs 1 to 16). First, the AFC_Process_Results routine is called to read the meter calculation results for all 16 meters (flow rate, accumulator, etc..). This rung also copies status of each meter (enabled or disabled) to EnableStatus variable.
   // Finally the meter will analyze the result of the modbus meter tpye and product group request to correct set each meter profile.
   10: XIC(AFC56.Flags.AFC_Stopped)[EQU(AFC56.inputbuffer[0],1000) ,EQU(AFC56.inputbuffer[0],1001) ]XIC(AFC56.ModbusMaster.Enable)EQU(AFC56.inputbuffer[3],AFC56.ModbusMaster.Command[AFC56.ModbusMaster.CommandIndex].Output.TransactionNumber)[MOV(AFC56.inputbuffer[2],AFC56.ModbusMaster.Command[AFC56.ModbusMaster.CommandIndex].Input.BID) ,XIC(AFC56.ModbusMaster.Command[AFC56.ModbusMaster.CommandIndex].Input.BID.0) OTE(AFC56.ModbusMaster.Command[AFC56.ModbusMaster.CommandIndex].Input.Pending) ,MOV(AFC56.inputbuffer[3],AFC56.ModbusMaster.Command[AFC56.ModbusMaster.CommandIndex].Input.TransactionNumber) ,MOV(AFC56.inputbuffer[4],AFC56.ModbusMaster.Command[AFC56.ModbusMaster.CommandIndex].Input.ErrorCode) ,XIO(AFC56.ModbusMaster.Command[AFC56.ModbusMaster.CommandIndex].Input.Pending) XIO(AFC56.ModbusMaster.Command[AFC56.ModbusMaster.CommandIndex].Input.BID.11) [XIO(AFC56.ModbusMaster.Command[AFC56.ModbusMaster.CommandIndex].Output.Config.DataType.Long) XIO(AFC56.ModbusMaster.Command[AFC56.ModbusMaster.CommandIndex].Output.Config.DataType.LongRemote) LIM(0,AFC56.ModbusMaster.Command[AFC56.ModbusMaster.CommandIndex].Output.Config.ElementCount,100) COP(AFC56.inputbuffer[5],AFC56.ModbusMaster.Command[AFC56.ModbusMaster.CommandIndex].Input.ReadData[0],AFC56.ModbusMaster.Command[AFC56.ModbusMaster.CommandIndex].Output.Config.ElementCount) ,[XIC(AFC56.ModbusMaster.Command[AFC56.ModbusMaster.CommandIndex].Output.Config.DataType.Long) ,XIC(AFC56.ModbusMaster.Command[AFC56.ModbusMaster.CommandIndex].Output.Config.DataType.LongRemote) ] [CPT(AFC56.Util.LongCount,AFC56.ModbusMaster.Command[AFC56.ModbusMaster.CommandIndex].Output.Config.ElementCount*2) ,LIM(0,AFC56.Util.LongCount,100) COP(AFC56.inputbuffer[5],AFC56.ModbusMaster.Command[AFC56.ModbusMaster.CommandIndex].Input.ReadData[0],AFC56.Util.LongCount) ] ] ];
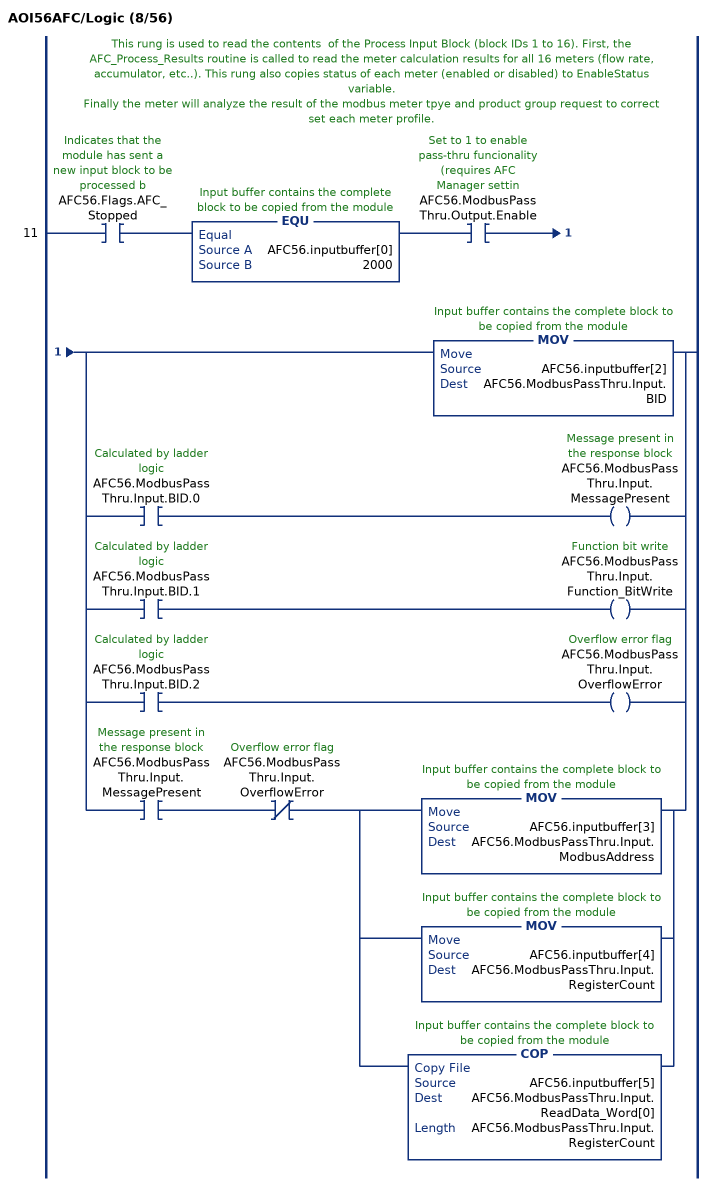
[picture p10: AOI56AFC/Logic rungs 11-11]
   // This rung is used to read the contents  of the Process Input Block (block IDs 1 to 16). First, the AFC_Process_Results routine is called to read the meter calculation results for all 16 meters (flow rate, accumulator, etc..). This rung also copies status of each meter (enabled or disabled) to EnableStatus variable.
   // Finally the meter will analyze the result of the modbus meter tpye and product group request to correct set each meter profile.
   11: XIC(AFC56.Flags.AFC_Stopped)EQU(AFC56.inputbuffer[0],2000)XIC(AFC56.ModbusPassThru.Output.Enable)[MOV(AFC56.inputbuffer[2],AFC56.ModbusPassThru.Input.BID) ,XIC(AFC56.ModbusPassThru.Input.BID.0) OTE(AFC56.ModbusPassThru.Input.MessagePresent) ,XIC(AFC56.ModbusPassThru.Input.BID.1) OTE(AFC56.ModbusPassThru.Input.Function_BitWrite) ,XIC(AFC56.ModbusPassThru.Input.BID.2) OTE(AFC56.ModbusPassThru.Input.OverflowError) ,XIC(AFC56.ModbusPassThru.Input.MessagePresent) XIO(AFC56.ModbusPassThru.Input.OverflowError) [MOV(AFC56.inputbuffer[3],AFC56.ModbusPassThru.Input.ModbusAddress) ,MOV(AFC56.inputbuffer[4],AFC56.ModbusPassThru.Input.RegisterCount) ,COP(AFC56.inputbuffer[5],AFC56.ModbusPassThru.Input.ReadData_Word[0],AFC56.ModbusPassThru.Input.RegisterCount) ] ];
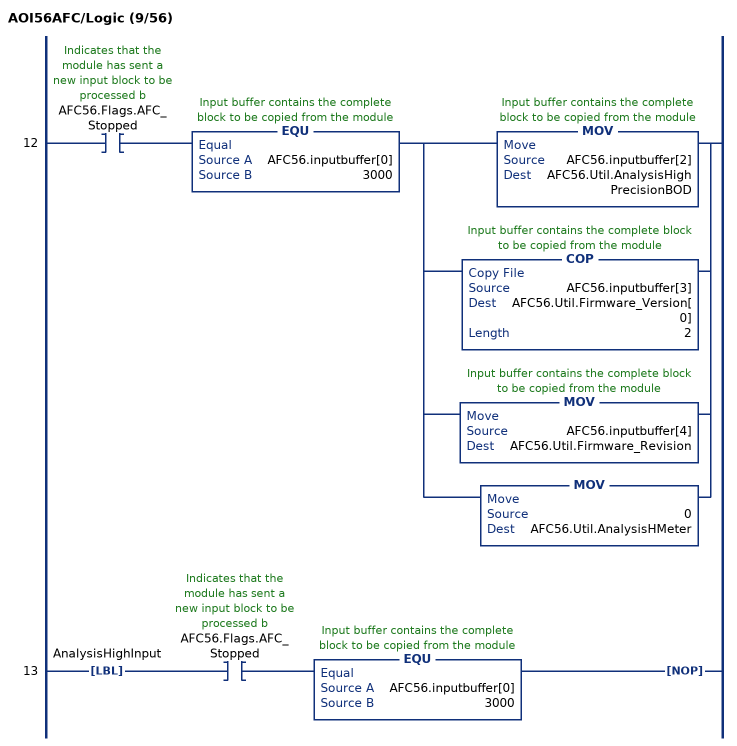
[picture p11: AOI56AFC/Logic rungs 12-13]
   12: XIC(AFC56.Flags.AFC_Stopped)EQU(AFC56.inputbuffer[0],3000)[MOV(AFC56.inputbuffer[2],AFC56.Util.AnalysisHighPrecisionBOD) ,COP(AFC56.inputbuffer[3],AFC56.Util.Firmware_Version[0],2) ,MOV(AFC56.inputbuffer[4],AFC56.Util.Firmware_Revision) ,MOV(0,AFC56.Util.AnalysisHMeter) ];
   13: LBL(AnalysisHighInput)XIC(AFC56.Flags.AFC_Stopped)EQU(AFC56.inputbuffer[0],3000)NOP();
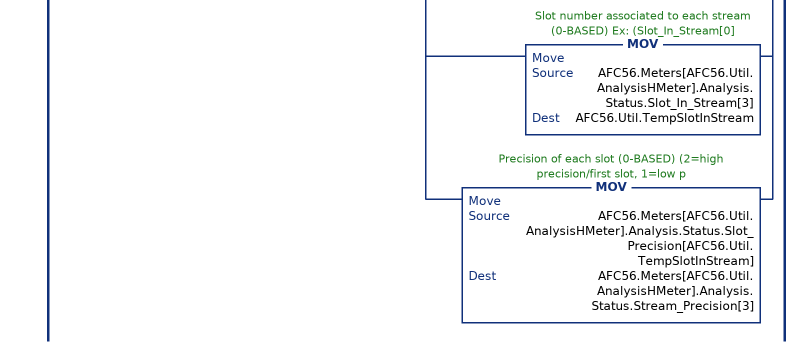
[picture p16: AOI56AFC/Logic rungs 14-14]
   14: XIC(AFC56.Flags.AFC_Stopped)EQU(AFC56.inputbuffer[0],3000)[MOV(0,AFC56.Util.SlotPrecision[0]) ,MOV(0,AFC56.Util.SlotPrecision[1]) ,MOV(0,AFC56.Util.SlotPrecision[2]) ,MOV(0,AFC56.Util.SlotPrecision[3]) ,MVM(AFC56.inputbuffer[5+AFC56.Util.AnalysisHMeter],3,AFC56.Util.SlotPrecision[0]) ,MOV(AFC56.Util.SlotPrecision[0],AFC56.Meters[AFC56.Util.AnalysisHMeter].Analysis.Status.Slot_Precision[0]) ,MVM(AFC56.inputbuffer[5+AFC56.Util.AnalysisHMeter],12,AFC56.Util.SlotPrecision[1]) ,DIV(AFC56.Util.SlotPrecision[1],4,AFC56.Meters[AFC56.Util.AnalysisHMeter].Analysis.Status.Slot_Precision[1]) ,MVM(AFC56.inputbuffer[5+AFC56.Util.AnalysisHMeter],48,AFC56.Util.SlotPrecision[2]) ,DIV(AFC56.Util.SlotPrecision[2],16,AFC56.Meters[AFC56.Util.AnalysisHMeter].Analysis.Status.Slot_Precision[2]) ,MVM(AFC56.inputbuffer[5+AFC56.Util.AnalysisHMeter],192,AFC56.Util.SlotPrecision[3]) ,DIV(AFC56.Util.SlotPrecision[3],64,AFC56.Meters[AFC56.Util.AnalysisHMeter].Analysis.Status.Slot_Precision[3]) ,MOV(0,AFC56.Util.SlotInStream[0]) ,MOV(0,AFC56.Util.SlotInStream[1]) ,MOV(0,AFC56.Util.SlotInStream[2]) ,MOV(0,AFC56.Util.SlotInStream[3]) ,MVM(AFC56.inputbuffer[5+AFC56.Util.AnalysisHMeter],768,AFC56.Util.SlotInStream[0]) ,DIV(AFC56.Util.SlotInStream[0],256,AFC56.Meters[AFC56.Util.AnalysisHMeter].Analysis.Status.Slot_In_Stream[0]) ,MVM(AFC56.inputbuffer[5+AFC56.Util.AnalysisHMeter],3072,AFC56.Util.SlotInStream[1]) ,DIV(AFC56.Util.SlotInStream[1],1024,AFC56.Meters[AFC56.Util.AnalysisHMeter].Analysis.Status.Slot_In_Stream[1]) ,MVM(AFC56.inputbuffer[5+AFC56.Util.AnalysisHMeter],12288,AFC56.Util.SlotInStream[2]) ,DIV(AFC56.Util.SlotInStream[2],4096,AFC56.Meters[AFC56.Util.AnalysisHMeter].Analysis.Status.Slot_In_Stream[2]) ,MVM(AFC56.inputbuffer[5+AFC56.Util.AnalysisHMeter],49152,AFC56.Util.SlotInStream[3]) ,DIV(AFC56.Util.SlotInStream[3],16384,AFC56.Meters[AFC56.Util.AnalysisHMeter].Analysis.Status.Slot_In_Stream[3]) ,MOV(AFC56.Meters[AFC56.Util.AnalysisHMeter].Analysis.Status.Slot_In_Stream[0],AFC56.Util.TempSlotInStream) ,MOV(AFC56.Meters[AFC56.Util.AnalysisHMeter].Analysis.Status.Slot_Precision[AFC56.Util.TempSlotInStream],AFC56.Meters[AFC56.Util.AnalysisHMeter].Analysis.Status.Stream_Precision[0]) ,MOV(AFC56.Meters[AFC56.Util.AnalysisHMeter].Analysis.Status.Slot_In_Stream[1],AFC56.Util.TempSlotInStream) ,MOV(AFC56.Meters[AFC56.Util.AnalysisHMeter].Analysis.Status.Slot_Precision[AFC56.Util.TempSlotInStream],AFC56.Meters[AFC56.Util.AnalysisHMeter].Analysis.Status.Stream_Precision[1]) ,MOV(AFC56.Meters[AFC56.Util.AnalysisHMeter].Analysis.Status.Slot_In_Stream[2],AFC56.Util.TempSlotInStream) ,MOV(AFC56.Meters[AFC56.Util.AnalysisHMeter].Analysis.Status.Slot_Precision[AFC56.Util.TempSlotInStream],AFC56.Meters[AFC56.Util.AnalysisHMeter].Analysis.Status.Stream_Precision[2]) ,MOV(AFC56.Meters[AFC56.Util.AnalysisHMeter].Analysis.Status.Slot_In_Stream[3],AFC56.Util.TempSlotInStream) ,MOV(AFC56.Meters[AFC56.Util.AnalysisHMeter].Analysis.Status.Slot_Precision[AFC56.Util.TempSlotInStream],AFC56.Meters[AFC56.Util.AnalysisHMeter].Analysis.Status.Stream_Precision[3]) ];
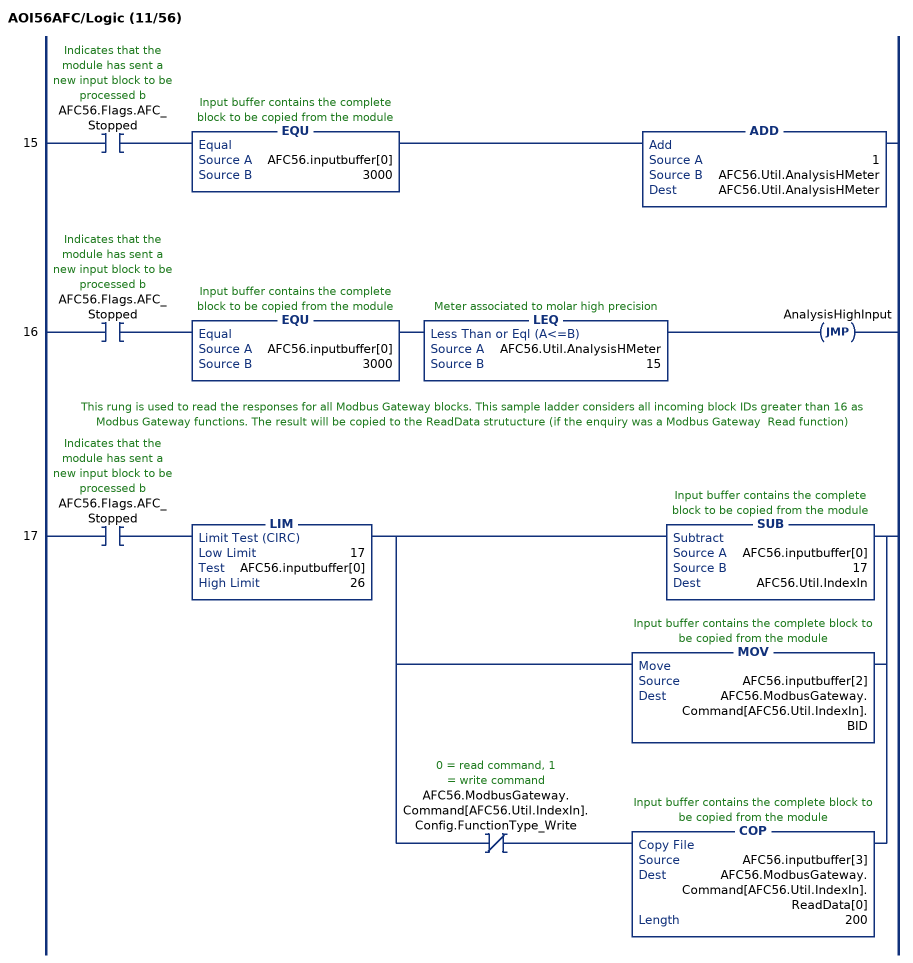
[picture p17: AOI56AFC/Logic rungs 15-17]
   15: XIC(AFC56.Flags.AFC_Stopped)EQU(AFC56.inputbuffer[0],3000)ADD(1,AFC56.Util.AnalysisHMeter,AFC56.Util.AnalysisHMeter);
   16: XIC(AFC56.Flags.AFC_Stopped)EQU(AFC56.inputbuffer[0],3000)LEQ(AFC56.Util.AnalysisHMeter,15)JMP(AnalysisHighInput);
   // This rung is used to read the responses for all Modbus Gateway blocks. This sample ladder considers all incoming block IDs greater than 16 as Modbus Gateway functions. The result will be copied to the ReadData strutucture (if the enquiry was a Modbus Gateway  Read function)
   17: XIC(AFC56.Flags.AFC_Stopped)LIM(17,AFC56.inputbuffer[0],26)[SUB(AFC56.inputbuffer[0],17,AFC56.Util.IndexIn) ,MOV(AFC56.inputbuffer[2],AFC56.ModbusGateway.Command[AFC56.Util.IndexIn].BID) ,XIO(AFC56.ModbusGateway.Command[AFC56.Util.IndexIn].Config.FunctionType_Write) COP(AFC56.inputbuffer[3],AFC56.ModbusGateway.Command[AFC56.Util.IndexIn].ReadData[0],200) ];
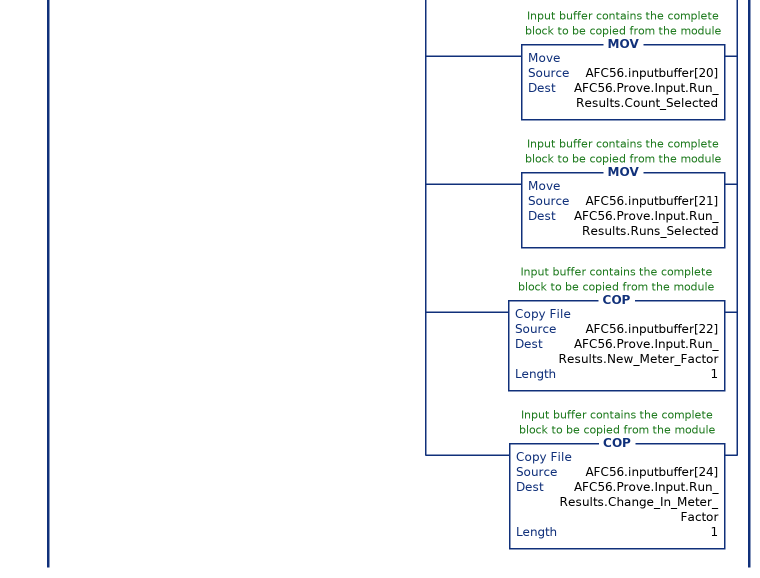
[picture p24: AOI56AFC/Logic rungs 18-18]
   18: XIC(AFC56.Flags.AFC_Stopped)EQU(AFC56.inputbuffer[0],5000)[XIC(AFC56.Util.Prover_Signals.1) OTU(AFC56.Prove.Output.Signals.EnableProve) ,XIC(AFC56.Util.Prover_Signals.2) OTU(AFC56.Prove.Output.Signals.AcceptProve) ,XIC(AFC56.Util.Prover_Signals.3) OTU(AFC56.Prove.Output.Signals.RejectProve) ,XIC(AFC56.Util.Prover_Signals.4) OTU(AFC56.Prove.Output.Signals.RunStart) ,XIC(AFC56.Util.Prover_Signals.5) OTU(AFC56.Prove.Output.Signals.RunComplete) ,XIC(AFC56.Util.Prover_Signals.6) OTU(AFC56.Prove.Output.Signals.RunCancel) ,XIC(AFC56.Util.Prover_Signals.7) OTU(AFC56.Prove.Output.Signals.RunDelete) ,XIC(AFC56.Util.Prover_Signals.9) OTU(AFC56.Prove.Output.Signals.PassComplete) ,XIC(AFC56.Util.Prover_Signals.12) OTU(AFC56.Prove.Output.Signals.PauseProve) ,XIC(AFC56.Util.Prover_Signals.14) OTU(AFC56.Prove.Output.Signals.AbortProve) ,MOV(AFC56.inputbuffer[3],AFC56.Prove.Input.Config.Type) ,MOV(AFC56.inputbuffer[4],AFC56.Prove.Input.Config.Options) ,MOV(AFC56.inputbuffer[5],AFC56.Prove.Input.Config.Runs_per_prove_total) ,MOV(AFC56.inputbuffer[6],AFC56.Prove.Input.Config.Runs_per_prove_selected) ,MOV(AFC56.inputbuffer[7],AFC56.Prove.Input.Config.Max_Runs_before_Abort) ,MOV(AFC56.inputbuffer[8],AFC56.Prove.Input.Config.Short_passes_per_run) ,XIC(AFC56.inputbuffer[12].0) OTL(AFC56.Prove.Input.Status.Prove_Accepted) ,XIO(AFC56.inputbuffer[12].0) OTU(AFC56.Prove.Input.Status.Prove_Accepted) ,XIC(AFC56.inputbuffer[12].1) OTL(AFC56.Prove.Input.Status.Meter_Factor_Applied) ,XIO(AFC56.inputbuffer[12].1) OTU(AFC56.Prove.Input.Status.Meter_Factor_Applied) ,XIC(AFC56.inputbuffer[12].2) OTL(AFC56.Prove.Input.Status.MF_Applied_To_Curve) ,XIO(AFC56.inputbuffer[12].2) OTU(AFC56.Prove.Input.Status.MF_Applied_To_Curve) ,XIC(AFC56.inputbuffer[12].3) OTL(AFC56.Prove.Input.Status.MF_Applied_To_Streams) ,XIO(AFC56.inputbuffer[12].3) OTU(AFC56.Prove.Input.Status.MF_Applied_To_Streams) ,XIC(AFC56.inputbuffer[12].4) OTL(AFC56.Prove.Input.Status.Prove_Rejected_By_Command) ,XIO(AFC56.inputbuffer[12].4) OTU(AFC56.Prove.Input.Status.Prove_Rejected_By_Command) ,XIC(AFC56.inputbuffer[12].5) OTL(AFC56.Prove.Input.Status.Prove_Rejected_No_Runs) ,XIO(AFC56.inputbuffer[12].5) OTU(AFC56.Prove.Input.Status.Prove_Rejected_No_Runs) ,XIC(AFC56.inputbuffer[12].6) OTL(AFC56.Prove.Input.Status.Prove_Rejected_Divide_By_0) ,XIO(AFC56.inputbuffer[12].6) OTU(AFC56.Prove.Input.Status.Prove_Rejected_Divide_By_0) ,XIC(AFC56.inputbuffer[12].8) OTL(AFC56.Prove.Input.Status.Prove_Enabled) ,[XIO(AFC56.inputbuffer[12].8) ,XIC(AFC56.Util.Prover_Signals.2) ,XIC(AFC56.Util.Prover_Signals.3) ,XIC(AFC56.Util.Prover_Signals.14) ] OTU(AFC56.Prove.Input.Status.Prove_Enabled) ,XIC(AFC56.inputbuffer[12].9) OTL(AFC56.Prove.Input.Status.Proving_Run_In_Progress) ,XIO(AFC56.inputbuffer[12].9) OTU(AFC56.Prove.Input.Status.Proving_Run_In_Progress) ,XIC(AFC56.inputbuffer[12].10) OTL(AFC56.Prove.Input.Status.Prove_Paused) ,XIO(AFC56.inputbuffer[12].10) OTU(AFC56.Prove.Input.Status.Prove_Paused) ,XIC(AFC56.inputbuffer[12].11) OTL(AFC56.Prove.Input.Status.Run_Cancelled) ,XIO(AFC56.inputbuffer[12].11) OTU(AFC56.Prove.Input.Status.Run_Cancelled) ,XIC(AFC56.inputbuffer[12].12) OTL(AFC56.Prove.Input.Status.Run_Timed_Out) ,XIO(AFC56.inputbuffer[12].12) OTU(AFC56.Prove.Input.Status.Run_Timed_Out) ,XIC(AFC56.inputbuffer[12].14) OTL(AFC56.Prove.Input.Status.Prove_Rejected_Abort) ,XIO(AFC56.inputbuffer[12].14) OTU(AFC56.Prove.Input.Status.Prove_Rejected_Abort) ,MOV(AFC56.inputbuffer[13],AFC56.Prove.Input.Error_Code) ,MOV(AFC56.inputbuffer[14],AFC56.Prove.Input.Prove_controls_echo) ,MOV(AFC56.inputbuffer[15],AFC56.Prove.Input.Requested_Meter_Echo) ,MOV(AFC56.inputbuffer[17],AFC56.Prove.Input.Requested_Curve_Point_Echo) ,COP(AFC56.inputbuffer[18],AFC56.Prove.Input.Run_Results.Count_Attempted,1) ,COP(AFC56.inputbuffer[19],AFC56.Prove.Input.Run_Results.Count_Completed,1) ,MOV(AFC56.inputbuffer[20],AFC56.Prove.Input.Run_Results.Count_Selected) ,MOV(AFC56.inputbuffer[21],AFC56.Prove.Input.Run_Results.Runs_Selected) ,COP(AFC56.inputbuffer[22],AFC56.Prove.Input.Run_Results.New_Meter_Factor,1) ,COP(AFC56.inputbuffer[24],AFC56.Prove.Input.Run_Results.Change_In_Meter_Factor,1) ];
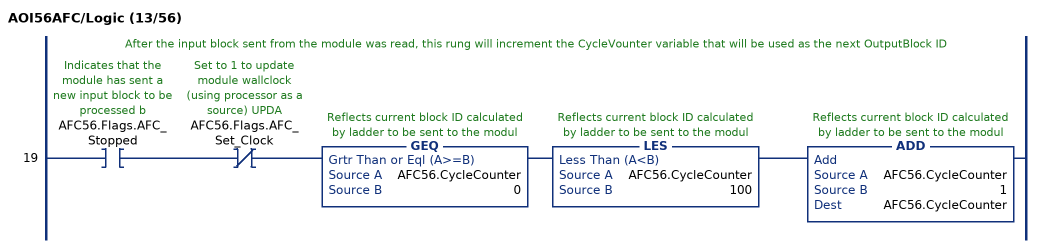
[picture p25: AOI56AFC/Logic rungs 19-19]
   // After the input block sent from the module was read, this rung will increment the CycleVounter variable that will be used as the next OutputBlock ID
   19: XIC(AFC56.Flags.AFC_Stopped)XIO(AFC56.Flags.AFC_Set_Clock)GEQ(AFC56.CycleCounter,0)LES(AFC56.CycleCounter,100)ADD(AFC56.CycleCounter,1,AFC56.CycleCounter);
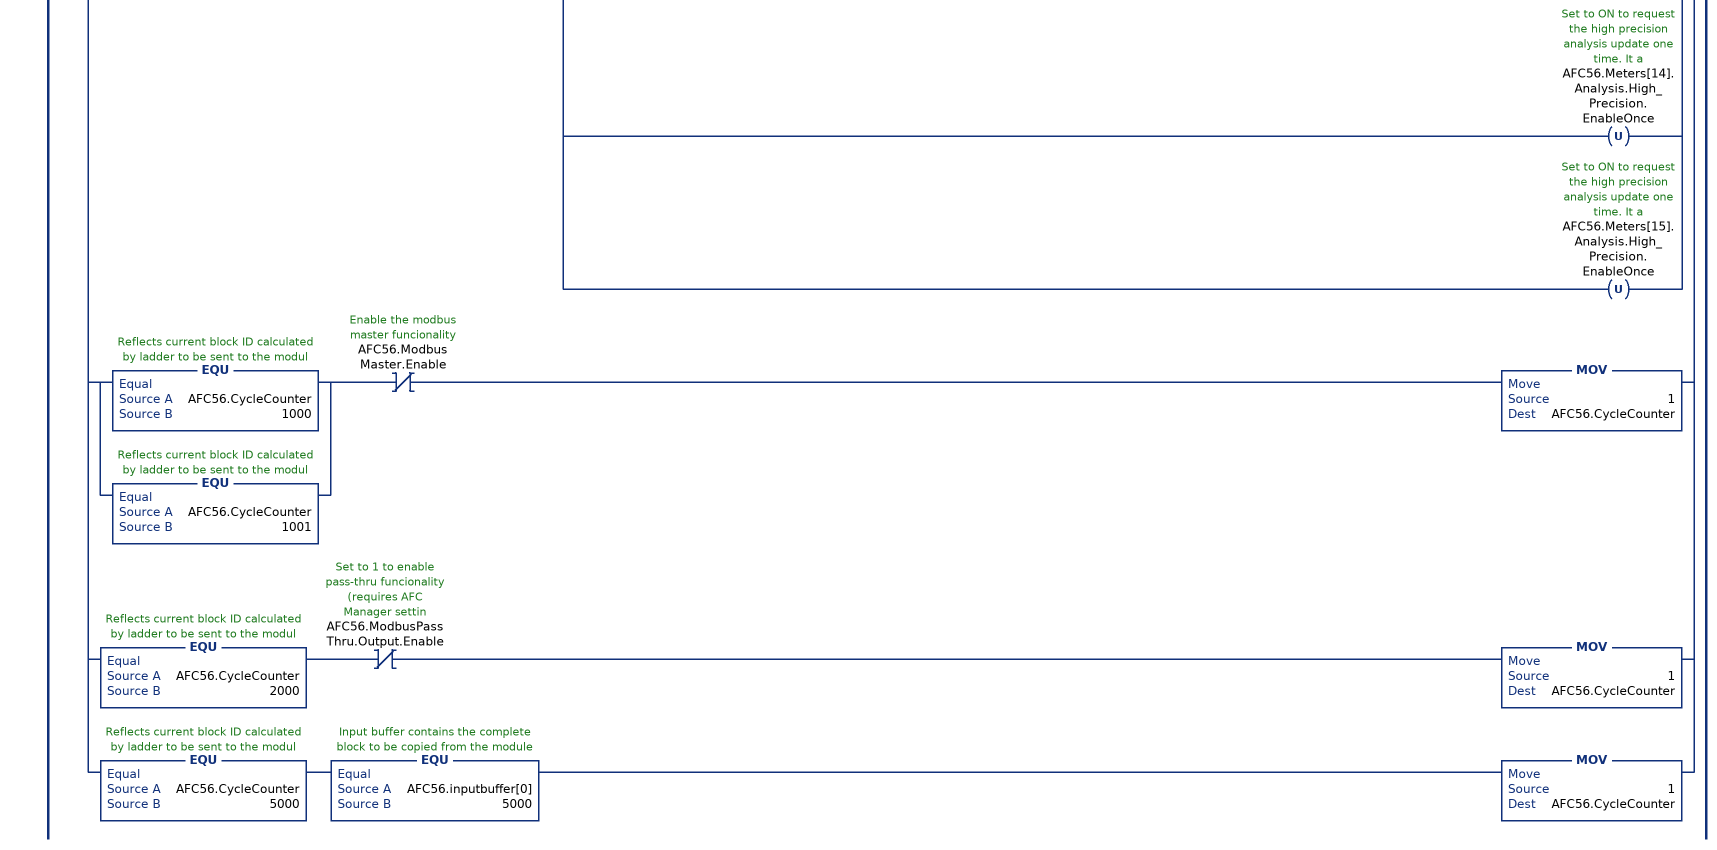
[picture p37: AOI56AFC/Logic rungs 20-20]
   // After the input block sent from the module was read, this rung will increment the CycleVounter variable that will be used as the next OutputBlock ID
   20: XIC(AFC56.Flags.AFC_Stopped)[SUB(AFC56.Util.CycleCounterRollover,1,AFC56.Util.LastRegularBlockID) ,EQU(AFC56.CycleCounter,AFC56.Util.CycleCounterRollover) EQU(AFC56.inputbuffer[0],AFC56.Util.LastRegularBlockID) [XIO(AFC56.ModbusMaster.Enable) XIO(AFC56.ModbusPassThru.Output.Enable) [XIO(AFC56.Prove.Input.Prove_Enabled) MOV(1,AFC56.CycleCounter) ,XIC(AFC56.Prove.Input.Prove_Enabled) MOV(5000,AFC56.CycleCounter) ] ,XIC(AFC56.ModbusMaster.Enable) [MOV(1000,AFC56.CycleCounter) ,OTU(AFC56.ModbusMaster.Command[AFC56.ModbusMaster.CommandIndex].Output.Config.Enable) ] ,XIO(AFC56.ModbusMaster.Enable) XIC(AFC56.ModbusPassThru.Output.Enable) MOV(2000,AFC56.CycleCounter) ,XIO(AFC56.ModbusMaster.Enable) XIO(AFC56.ModbusPassThru.Output.Enable) [XIC(AFC56.Meters[0].Analysis.Status.Update) ,XIC(AFC56.Meters[1].Analysis.Status.Update) ,XIC(AFC56.Meters[2].Analysis.Status.Update) ,XIC(AFC56.Meters[3].Analysis.Status.Update) ,XIC(AFC56.Meters[4].Analysis.Status.Update) ,XIC(AFC56.Meters[5].Analysis.Status.Update) ,XIC(AFC56.Meters[6].Analysis.Status.Update) ,XIC(AFC56.Meters[7].Analysis.Status.Update) ,XIC(AFC56.Meters[8].Analysis.Status.Update) ,XIC(AFC56.Meters[9].Analysis.Status.Update) ,XIC(AFC56.Meters[10].Analysis.Status.Update) ,XIC(AFC56.Meters[11].Analysis.Status.Update) ,XIC(AFC56.Meters[12].Analysis.Status.Update) ,XIC(AFC56.Meters[13].Analysis.Status.Update) ,XIC(AFC56.Meters[14].Analysis.Status.Update) ,XIC(AFC56.Meters[15].Analysis.Status.Update) ] XIC(AFC56.inputbuffer[247].11) MOV(3000,AFC56.CycleCounter) ,XIO(AFC56.ModbusMaster.Enable) XIO(AFC56.ModbusPassThru.Output.Enable) [LES(AFC56.CycleCounter,3000) ,GRT(AFC56.CycleCounter,3004) ] [XIC(AFC56.Meters[0].Analysis.High_Precision.EnableOnce) ,XIC(AFC56.Meters[1].Analysis.High_Precision.EnableOnce) ,XIC(AFC56.Meters[2].Analysis.High_Precision.EnableOnce) ,XIC(AFC56.Meters[3].Analysis.High_Precision.EnableOnce) ,XIC(AFC56.Meters[4].Analysis.High_Precision.EnableOnce) ,XIC(AFC56.Meters[5].Analysis.High_Precision.EnableOnce) ,XIC(AFC56.Meters[6].Analysis.High_Precision.EnableOnce) ,XIC(AFC56.Meters[7].Analysis.High_Precision.EnableOnce) ,XIC(AFC56.Meters[8].Analysis.High_Precision.EnableOnce) ,XIC(AFC56.Meters[9].Analysis.High_Precision.EnableOnce) ,XIC(AFC56.Meters[10].Analysis.High_Precision.EnableOnce) ,XIC(AFC56.Meters[11].Analysis.High_Precision.EnableOnce) ,XIC(AFC56.Meters[12].Analysis.High_Precision.EnableOnce) ,XIC(AFC56.Meters[13].Analysis.High_Precision.EnableOnce) ,XIC(AFC56.Meters[13].Analysis.High_Precision.EnableOnce) ,XIC(AFC56.Meters[14].Analysis.High_Precision.EnableOnce) ,XIC(AFC56.Meters[15].Analysis.High_Precision.EnableOnce) ] XIC(AFC56.inputbuffer[247].11) MOV(3001,AFC56.CycleCounter) ] ,EQU(AFC56.CycleCounter,1000) EQU(AFC56.inputbuffer[0],1000) [MOV(1001,AFC56.CycleCounter) ,OTL(AFC56.ModbusMaster.Command[AFC56.ModbusMaster.CommandIndex].Output.Config.Enable) ] ,EQU(AFC56.CycleCounter,1001) EQU(AFC56.inputbuffer[0],1001) [XIC(AFC56.ModbusPassThru.Output.Enable) MOV(2000,AFC56.CycleCounter) ,XIO(AFC56.ModbusPassThru.Output.Enable) MOV(1,AFC56.CycleCounter) ] ,EQU(AFC56.CycleCounter,2000) EQU(AFC56.inputbuffer[0],2000) MOV(1,AFC56.CycleCounter) ,EQU(AFC56.CycleCounter,3001) EQU(AFC56.inputbuffer[0],3001) MOV(3002,AFC56.CycleCounter) ,EQU(AFC56.CycleCounter,3002) EQU(AFC56.inputbuffer[0],3002) MOV(3003,AFC56.CycleCounter) ,EQU(AFC56.CycleCounter,3003) EQU(AFC56.inputbuffer[0],3003) MOV(3004,AFC56.CycleCounter) ,EQU(AFC56.CycleCounter,3004) EQU(AFC56.inputbuffer[0],3004) [XIO(AFC56.Prove.Input.Prove_Enabled) MOV(1,AFC56.CycleCounter) ,XIC(AFC56.Prove.Input.Prove_Enabled) MOV(5000,AFC56.CycleCounter) ,OTU(AFC56.Meters[0].Analysis.High_Precision.EnableOnce) ,OTU(AFC56.Meters[1].Analysis.High_Precision.EnableOnce) ,OTU(AFC56.Meters[2].Analysis.High_Precision.EnableOnce) ,OTU(AFC56.Meters[3].Analysis.High_Precision.EnableOnce) ,OTU(AFC56.Meters[4].Analysis.High_Precision.EnableOnce) ,OTU(AFC56.Meters[5].Analysis.High_Precision.EnableOnce) ,OTU(AFC56.Meters[6].Analysis.High_Precision.EnableOnce) ,OTU(AFC56.Meters[7].Analysis.High_Precision.EnableOnce) ,OTU(AFC56.Meters[8].Analysis.High_Precision.EnableOnce) ,OTU(AFC56.Meters[9].Analysis.High_Precision.EnableOnce) ,OTU(AFC56.Meters[10].Analysis.High_Precision.EnableOnce) ,OTU(AFC56.Meters[11].Analysis.High_Precision.EnableOnce) ,OTU(AFC56.Meters[12].Analysis.High_Precision.EnableOnce) ,OTU(AFC56.Meters[13].Analysis.High_Precision.EnableOnce) ,OTU(AFC56.Meters[13].Analysis.High_Precision.EnableOnce) ,OTU(AFC56.Meters[14].Analysis.High_Precision.EnableOnce) ,OTU(AFC56.Meters[15].Analysis.High_Precision.EnableOnce) ] ,EQU(AFC56.CycleCounter,3000) EQU(AFC56.inputbuffer[0],3000) [MOV(1,AFC56.CycleCounter) ,OTU(AFC56.Meters[0].Analysis.High_Precision.EnableOnce) ,OTU(AFC56.Meters[1].Analysis.High_Precision.EnableOnce) ,OTU(AFC56.Meters[2].Analysis.High_Precision.EnableOnce) ,OTU(AFC56.Meters[3].Analysis.High_Precision.EnableOnce) ,OTU(AFC56.Meters[4].Analysis.High_Precision.EnableOnce) ,OTU(AFC56.Meters[5].Analysis.High_Precision.EnableOnce) ,OTU(AFC56.Meters[6].Analysis.High_Precision.EnableOnce) ,OTU(AFC56.Meters[7].Analysis.High_Precision.EnableOnce) ,OTU(AFC56.Meters[8].Analysis.High_Precision.EnableOnce) ,OTU(AFC56.Meters[9].Analysis.High_Precision.EnableOnce) ,OTU(AFC56.Meters[10].Analysis.High_Precision.EnableOnce) ,OTU(AFC56.Meters[11].Analysis.High_Precision.EnableOnce) ,OTU(AFC56.Meters[12].Analysis.High_Precision.EnableOnce) ,OTU(AFC56.Meters[13].Analysis.High_Precision.EnableOnce) ,OTU(AFC56.Meters[13].Analysis.High_Precision.EnableOnce) ,OTU(AFC56.Meters[14].Analysis.High_Precision.EnableOnce) ,OTU(AFC56.Meters[15].Analysis.High_Precision.EnableOnce) ] ,[EQU(AFC56.CycleCounter,1000) ,EQU(AFC56.CycleCounter,1001) ] XIO(AFC56.ModbusMaster.Enable) MOV(1,AFC56.CycleCounter) ,EQU(AFC56.CycleCounter,2000) XIO(AFC56.ModbusPassThru.Output.Enable) MOV(1,AFC56.CycleCounter) ,EQU(AFC56.CycleCounter,5000) EQU(AFC56.inputbuffer[0],5000) MOV(1,AFC56.CycleCounter) ];
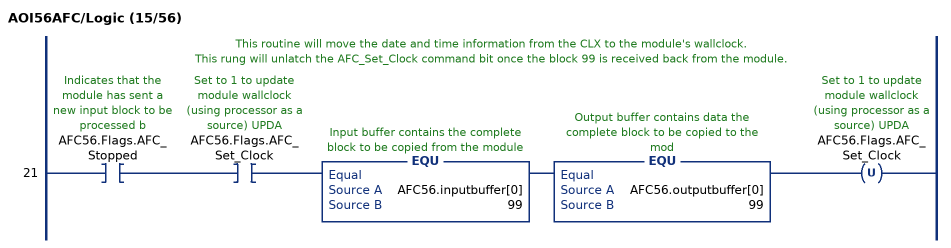
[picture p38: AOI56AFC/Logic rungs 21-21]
   // This routine will move the date and time information from the CLX to the module's wallclock.
   // This rung will unlatch the AFC_Set_Clock command bit once the block 99 is received back from the module.
   21: XIC(AFC56.Flags.AFC_Stopped)XIC(AFC56.Flags.AFC_Set_Clock)EQU(AFC56.inputbuffer[0],99)EQU(AFC56.outputbuffer[0],99)OTU(AFC56.Flags.AFC_Set_Clock);
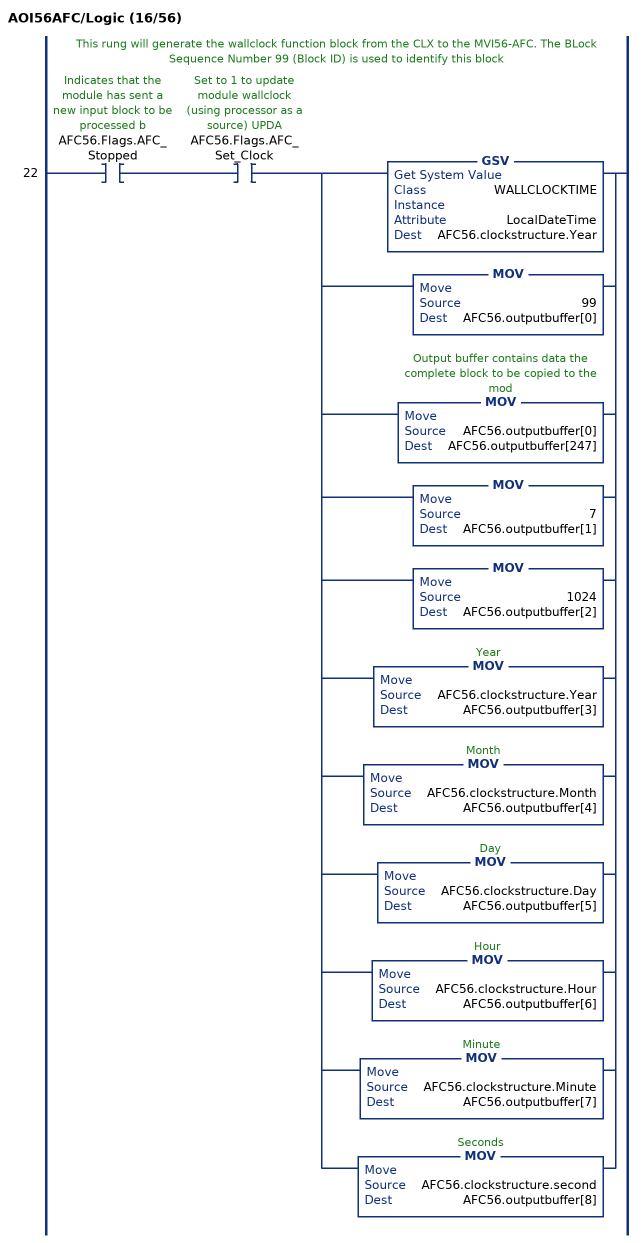
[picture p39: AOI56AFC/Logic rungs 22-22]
   // This rung will generate the wallclock function block from the CLX to the MVI56-AFC. The BLock Sequence Number 99 (Block ID) is used to identify this block
   22: XIC(AFC56.Flags.AFC_Stopped)XIC(AFC56.Flags.AFC_Set_Clock)[GSV(WALLCLOCKTIME,,LocalDateTime,AFC56.clockstructure.Year) ,MOV(99,AFC56.outputbuffer[0]) ,MOV(AFC56.outputbuffer[0],AFC56.outputbuffer[247]) ,MOV(7,AFC56.outputbuffer[1]) ,MOV(1024,AFC56.outputbuffer[2]) ,MOV(AFC56.clockstructure.Year,AFC56.outputbuffer[3]) ,MOV(AFC56.clockstructure.Month,AFC56.outputbuffer[4]) ,MOV(AFC56.clockstructure.Day,AFC56.outputbuffer[5]) ,MOV(AFC56.clockstructure.Hour,AFC56.outputbuffer[6]) ,MOV(AFC56.clockstructure.Minute,AFC56.outputbuffer[7]) ,MOV(AFC56.clockstructure.second,AFC56.outputbuffer[8]) ];
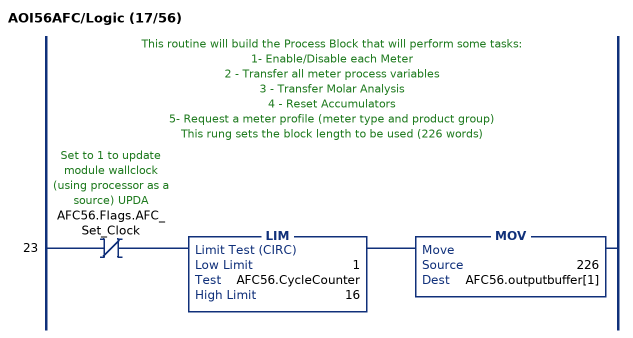
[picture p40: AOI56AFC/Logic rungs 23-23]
   // This routine will build the Process Block that will perform some tasks:
   // 1- Enable/Disable each Meter
   // 2 - Transfer all meter process variables
   // 3 - Transfer Molar Analysis
   // 4 - Reset Accumulators
   // 5- Request a meter profile (meter type and product group)
   // This rung sets the block length to be used (226 words)
   23: XIO(AFC56.Flags.AFC_Set_Clock)LIM(1,AFC56.CycleCounter,16)MOV(226,AFC56.outputbuffer[1]);
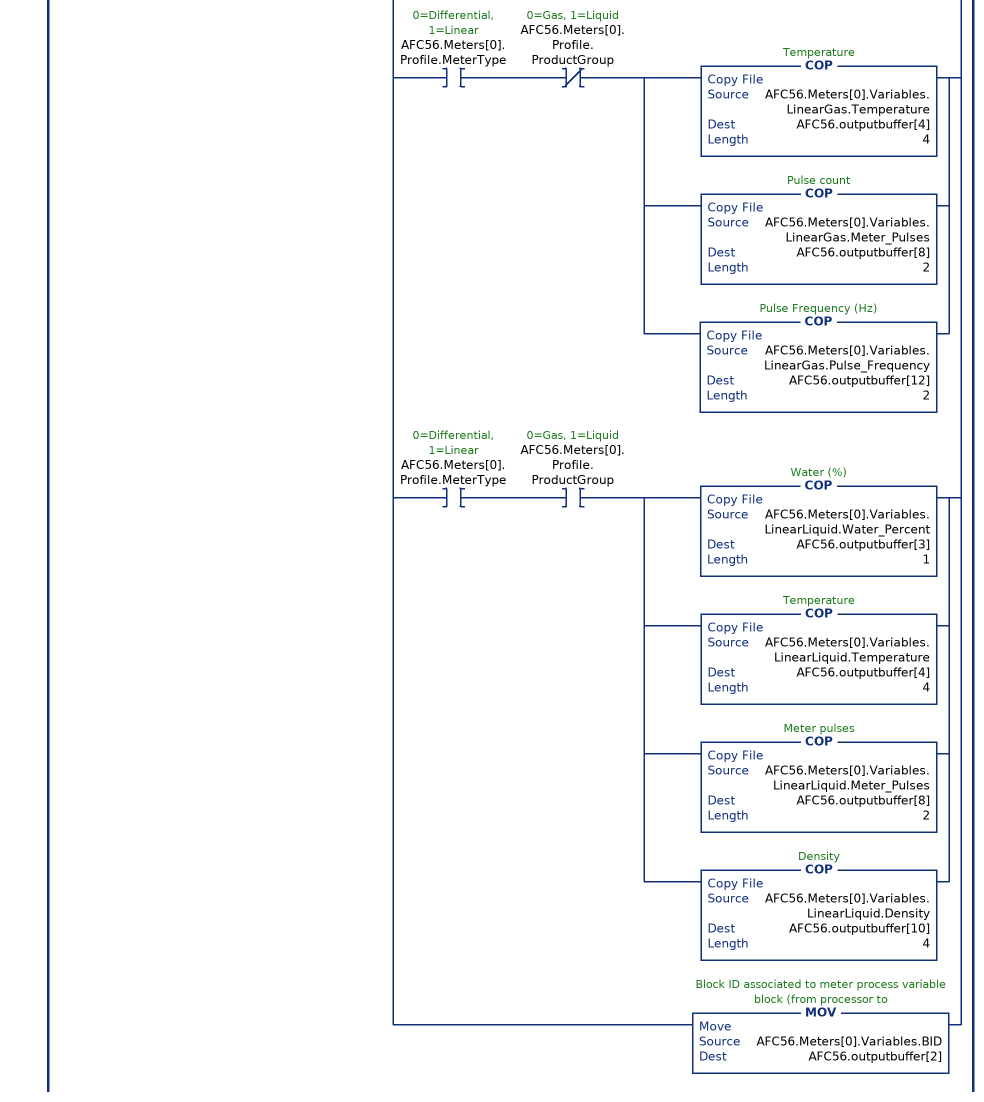
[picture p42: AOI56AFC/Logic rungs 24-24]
   // This routine will copy the meter variables  for all 16 meters from the AFC56.Meters[].Variables data structure to the outputbuffer[] array. The logic will copy the variables according to each meter profile (meter type and product group).
   // This routine also verifies each EnableStatus variable in order to unlatch the meter disable or enable commands.
   24: XIO(AFC56.Flags.AFC_Set_Clock)LIM(1,AFC56.CycleCounter,16)[ADD(1,8192,AFC56.Meters[0].Variables.BID) ,XIO(AFC56.EnableStatus.Meter1) [OTE(AFC56.Meters[0].Variables.BID.8) ,OTU(AFC56.DisableMeter.Meter1) ] ,XIC(AFC56.EnableStatus.Meter1) OTU(AFC56.EnableMeter.Meter1) ,XIO(AFC56.Meters[0].Profile.MeterType) XIO(AFC56.Meters[0].Profile.ProductGroup) COP(AFC56.Meters[0].Variables.DifferentialGas.Temperature,AFC56.outputbuffer[4],6) ,XIO(AFC56.Meters[0].Profile.MeterType) XIC(AFC56.Meters[0].Profile.ProductGroup) [COP(AFC56.Meters[0].Variables.DifferentialLiquid.Water_Percent,AFC56.outputbuffer[3],1) ,COP(AFC56.Meters[0].Variables.DifferentialLiquid.Temperature,AFC56.outputbuffer[4],8) ] ,XIC(AFC56.Meters[0].Profile.MeterType) XIO(AFC56.Meters[0].Profile.ProductGroup) [COP(AFC56.Meters[0].Variables.LinearGas.Temperature,AFC56.outputbuffer[4],4) ,COP(AFC56.Meters[0].Variables.LinearGas.Meter_Pulses,AFC56.outputbuffer[8],2) ,COP(AFC56.Meters[0].Variables.LinearGas.Pulse_Frequency,AFC56.outputbuffer[12],2) ] ,XIC(AFC56.Meters[0].Profile.MeterType) XIC(AFC56.Meters[0].Profile.ProductGroup) [COP(AFC56.Meters[0].Variables.LinearLiquid.Water_Percent,AFC56.outputbuffer[3],1) ,COP(AFC56.Meters[0].Variables.LinearLiquid.Temperature,AFC56.outputbuffer[4],4) ,COP(AFC56.Meters[0].Variables.LinearLiquid.Meter_Pulses,AFC56.outputbuffer[8],2) ,COP(AFC56.Meters[0].Variables.LinearLiquid.Density,AFC56.outputbuffer[10],4) ] ,MOV(AFC56.Meters[0].Variables.BID,AFC56.outputbuffer[2]) ];
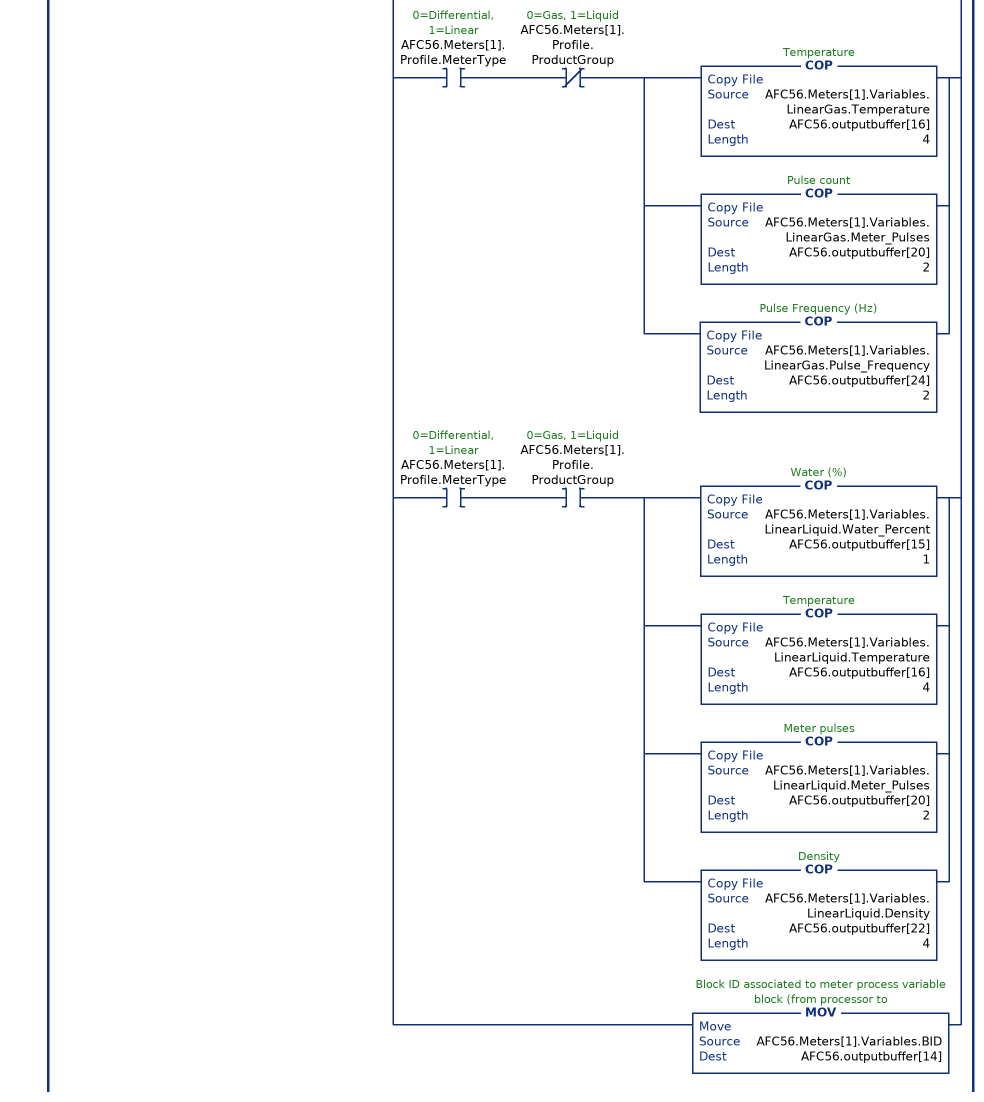
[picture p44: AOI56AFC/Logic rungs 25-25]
   25: XIO(AFC56.Flags.AFC_Set_Clock)LIM(1,AFC56.CycleCounter,16)[ADD(2,8192,AFC56.Meters[1].Variables.BID) ,XIO(AFC56.EnableStatus.Meter2) [OTE(AFC56.Meters[1].Variables.BID.8) ,OTU(AFC56.DisableMeter.Meter2) ] ,XIC(AFC56.EnableStatus.Meter2) OTU(AFC56.EnableMeter.Meter2) ,XIO(AFC56.Meters[1].Profile.MeterType) XIO(AFC56.Meters[1].Profile.ProductGroup) COP(AFC56.Meters[1].Variables.DifferentialGas.Temperature,AFC56.outputbuffer[16],6) ,XIO(AFC56.Meters[1].Profile.MeterType) XIC(AFC56.Meters[1].Profile.ProductGroup) [COP(AFC56.Meters[1].Variables.DifferentialLiquid.Water_Percent,AFC56.outputbuffer[15],1) ,COP(AFC56.Meters[1].Variables.DifferentialLiquid.Temperature,AFC56.outputbuffer[16],8) ] ,XIC(AFC56.Meters[1].Profile.MeterType) XIO(AFC56.Meters[1].Profile.ProductGroup) [COP(AFC56.Meters[1].Variables.LinearGas.Temperature,AFC56.outputbuffer[16],4) ,COP(AFC56.Meters[1].Variables.LinearGas.Meter_Pulses,AFC56.outputbuffer[20],2) ,COP(AFC56.Meters[1].Variables.LinearGas.Pulse_Frequency,AFC56.outputbuffer[24],2) ] ,XIC(AFC56.Meters[1].Profile.MeterType) XIC(AFC56.Meters[1].Profile.ProductGroup) [COP(AFC56.Meters[1].Variables.LinearLiquid.Water_Percent,AFC56.outputbuffer[15],1) ,COP(AFC56.Meters[1].Variables.LinearLiquid.Temperature,AFC56.outputbuffer[16],4) ,COP(AFC56.Meters[1].Variables.LinearLiquid.Meter_Pulses,AFC56.outputbuffer[20],2) ,COP(AFC56.Meters[1].Variables.LinearLiquid.Density,AFC56.outputbuffer[22],4) ] ,MOV(AFC56.Meters[1].Variables.BID,AFC56.outputbuffer[14]) ];
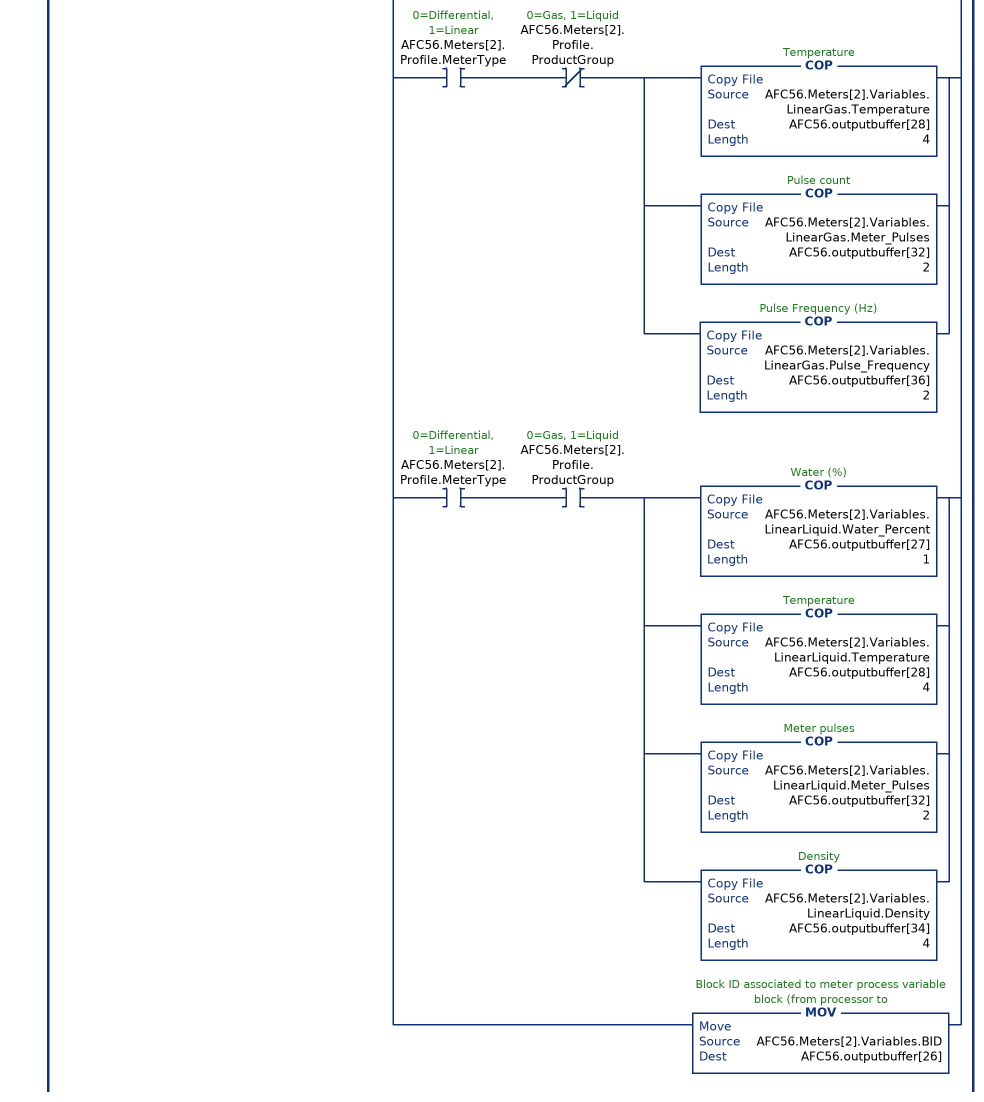
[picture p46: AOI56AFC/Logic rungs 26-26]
   26: XIO(AFC56.Flags.AFC_Set_Clock)LIM(1,AFC56.CycleCounter,16)[ADD(3,8192,AFC56.Meters[2].Variables.BID) ,XIO(AFC56.EnableStatus.Meter3) [OTE(AFC56.Meters[2].Variables.BID.8) ,OTU(AFC56.DisableMeter.Meter3) ] ,XIC(AFC56.EnableStatus.Meter3) OTU(AFC56.EnableMeter.Meter3) ,XIO(AFC56.Meters[2].Profile.MeterType) XIO(AFC56.Meters[2].Profile.ProductGroup) COP(AFC56.Meters[2].Variables.DifferentialGas.Temperature,AFC56.outputbuffer[28],6) ,XIO(AFC56.Meters[2].Profile.MeterType) XIC(AFC56.Meters[2].Profile.ProductGroup) [COP(AFC56.Meters[2].Variables.DifferentialLiquid.Water_Percent,AFC56.outputbuffer[27],1) ,COP(AFC56.Meters[2].Variables.DifferentialLiquid.Temperature,AFC56.outputbuffer[28],8) ] ,XIC(AFC56.Meters[2].Profile.MeterType) XIO(AFC56.Meters[2].Profile.ProductGroup) [COP(AFC56.Meters[2].Variables.LinearGas.Temperature,AFC56.outputbuffer[28],4) ,COP(AFC56.Meters[2].Variables.LinearGas.Meter_Pulses,AFC56.outputbuffer[32],2) ,COP(AFC56.Meters[2].Variables.LinearGas.Pulse_Frequency,AFC56.outputbuffer[36],2) ] ,XIC(AFC56.Meters[2].Profile.MeterType) XIC(AFC56.Meters[2].Profile.ProductGroup) [COP(AFC56.Meters[2].Variables.LinearLiquid.Water_Percent,AFC56.outputbuffer[27],1) ,COP(AFC56.Meters[2].Variables.LinearLiquid.Temperature,AFC56.outputbuffer[28],4) ,COP(AFC56.Meters[2].Variables.LinearLiquid.Meter_Pulses,AFC56.outputbuffer[32],2) ,COP(AFC56.Meters[2].Variables.LinearLiquid.Density,AFC56.outputbuffer[34],4) ] ,MOV(AFC56.Meters[2].Variables.BID,AFC56.outputbuffer[26]) ];
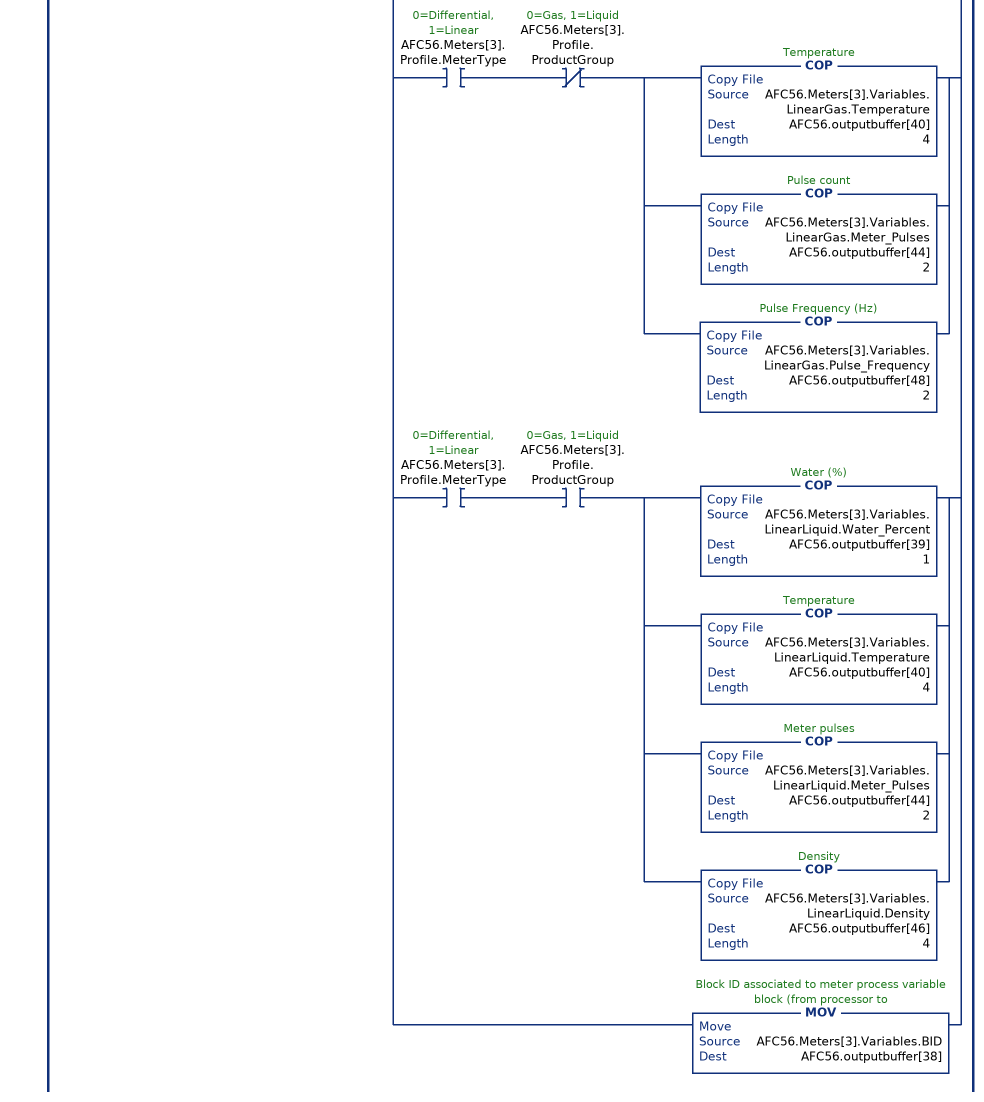
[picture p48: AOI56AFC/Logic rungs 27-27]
   27: XIO(AFC56.Flags.AFC_Set_Clock)LIM(1,AFC56.CycleCounter,16)[ADD(4,8192,AFC56.Meters[3].Variables.BID) ,XIO(AFC56.EnableStatus.Meter4) [OTE(AFC56.Meters[3].Variables.BID.8) ,OTU(AFC56.DisableMeter.Meter4) ] ,XIC(AFC56.EnableStatus.Meter4) OTU(AFC56.EnableMeter.Meter4) ,XIO(AFC56.Meters[3].Profile.MeterType) XIO(AFC56.Meters[3].Profile.ProductGroup) COP(AFC56.Meters[3].Variables.DifferentialGas.Temperature,AFC56.outputbuffer[40],6) ,XIO(AFC56.Meters[3].Profile.MeterType) XIC(AFC56.Meters[3].Profile.ProductGroup) [COP(AFC56.Meters[3].Variables.DifferentialLiquid.Water_Percent,AFC56.outputbuffer[39],1) ,COP(AFC56.Meters[3].Variables.DifferentialLiquid.Temperature,AFC56.outputbuffer[40],8) ] ,XIC(AFC56.Meters[3].Profile.MeterType) XIO(AFC56.Meters[3].Profile.ProductGroup) [COP(AFC56.Meters[3].Variables.LinearGas.Temperature,AFC56.outputbuffer[40],4) ,COP(AFC56.Meters[3].Variables.LinearGas.Meter_Pulses,AFC56.outputbuffer[44],2) ,COP(AFC56.Meters[3].Variables.LinearGas.Pulse_Frequency,AFC56.outputbuffer[48],2) ] ,XIC(AFC56.Meters[3].Profile.MeterType) XIC(AFC56.Meters[3].Profile.ProductGroup) [COP(AFC56.Meters[3].Variables.LinearLiquid.Water_Percent,AFC56.outputbuffer[39],1) ,COP(AFC56.Meters[3].Variables.LinearLiquid.Temperature,AFC56.outputbuffer[40],4) ,COP(AFC56.Meters[3].Variables.LinearLiquid.Meter_Pulses,AFC56.outputbuffer[44],2) ,COP(AFC56.Meters[3].Variables.LinearLiquid.Density,AFC56.outputbuffer[46],4) ] ,MOV(AFC56.Meters[3].Variables.BID,AFC56.outputbuffer[38]) ];
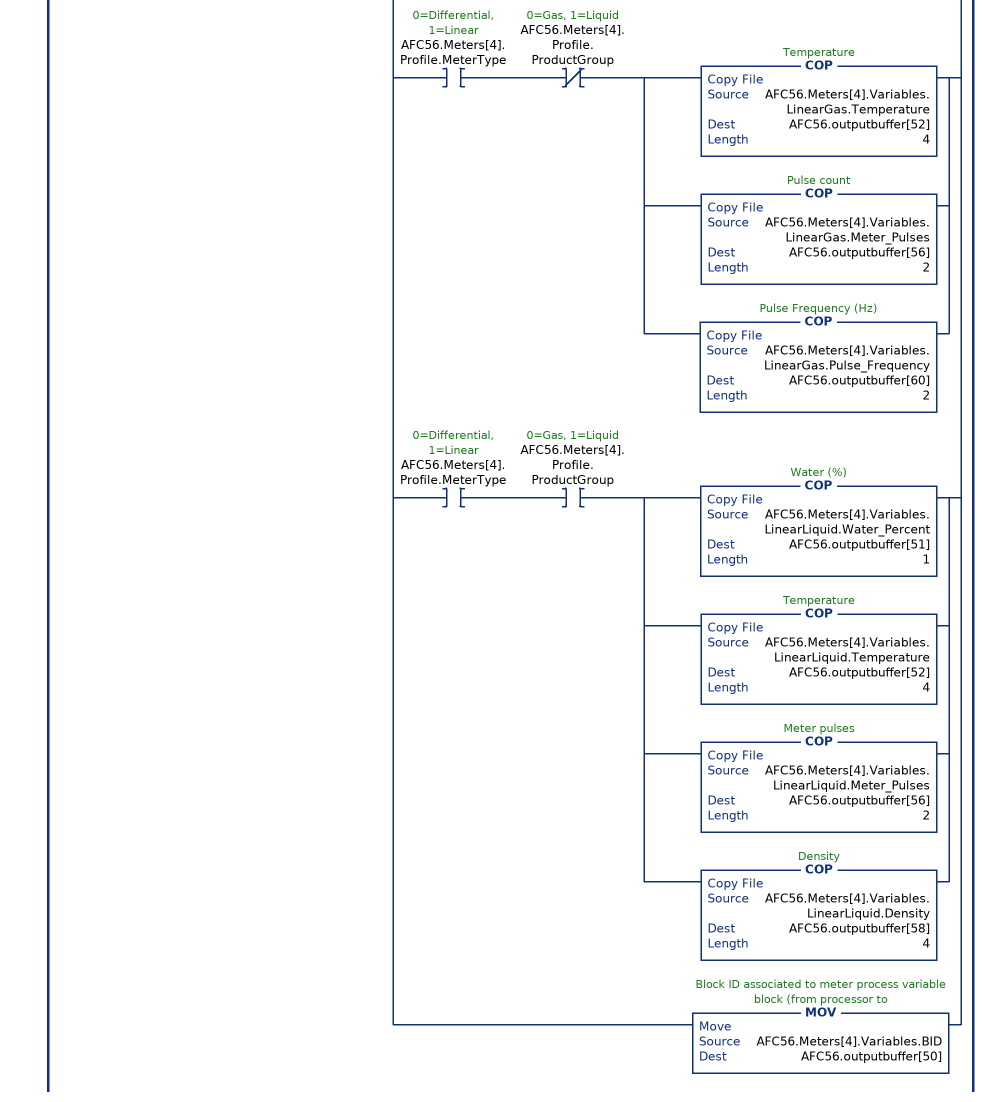
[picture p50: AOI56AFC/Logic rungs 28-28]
   28: XIO(AFC56.Flags.AFC_Set_Clock)LIM(1,AFC56.CycleCounter,16)[ADD(5,8192,AFC56.Meters[4].Variables.BID) ,XIO(AFC56.EnableStatus.Meter5) [OTE(AFC56.Meters[4].Variables.BID.8) ,OTU(AFC56.DisableMeter.Meter5) ] ,XIC(AFC56.EnableStatus.Meter5) OTU(AFC56.EnableMeter.Meter5) ,XIO(AFC56.Meters[4].Profile.MeterType) XIO(AFC56.Meters[4].Profile.ProductGroup) COP(AFC56.Meters[4].Variables.DifferentialGas.Temperature,AFC56.outputbuffer[52],6) ,XIO(AFC56.Meters[4].Profile.MeterType) XIC(AFC56.Meters[4].Profile.ProductGroup) [COP(AFC56.Meters[4].Variables.DifferentialLiquid.Water_Percent,AFC56.outputbuffer[51],1) ,COP(AFC56.Meters[4].Variables.DifferentialLiquid.Temperature,AFC56.outputbuffer[52],8) ] ,XIC(AFC56.Meters[4].Profile.MeterType) XIO(AFC56.Meters[4].Profile.ProductGroup) [COP(AFC56.Meters[4].Variables.LinearGas.Temperature,AFC56.outputbuffer[52],4) ,COP(AFC56.Meters[4].Variables.LinearGas.Meter_Pulses,AFC56.outputbuffer[56],2) ,COP(AFC56.Meters[4].Variables.LinearGas.Pulse_Frequency,AFC56.outputbuffer[60],2) ] ,XIC(AFC56.Meters[4].Profile.MeterType) XIC(AFC56.Meters[4].Profile.ProductGroup) [COP(AFC56.Meters[4].Variables.LinearLiquid.Water_Percent,AFC56.outputbuffer[51],1) ,COP(AFC56.Meters[4].Variables.LinearLiquid.Temperature,AFC56.outputbuffer[52],4) ,COP(AFC56.Meters[4].Variables.LinearLiquid.Meter_Pulses,AFC56.outputbuffer[56],2) ,COP(AFC56.Meters[4].Variables.LinearLiquid.Density,AFC56.outputbuffer[58],4) ] ,MOV(AFC56.Meters[4].Variables.BID,AFC56.outputbuffer[50]) ];
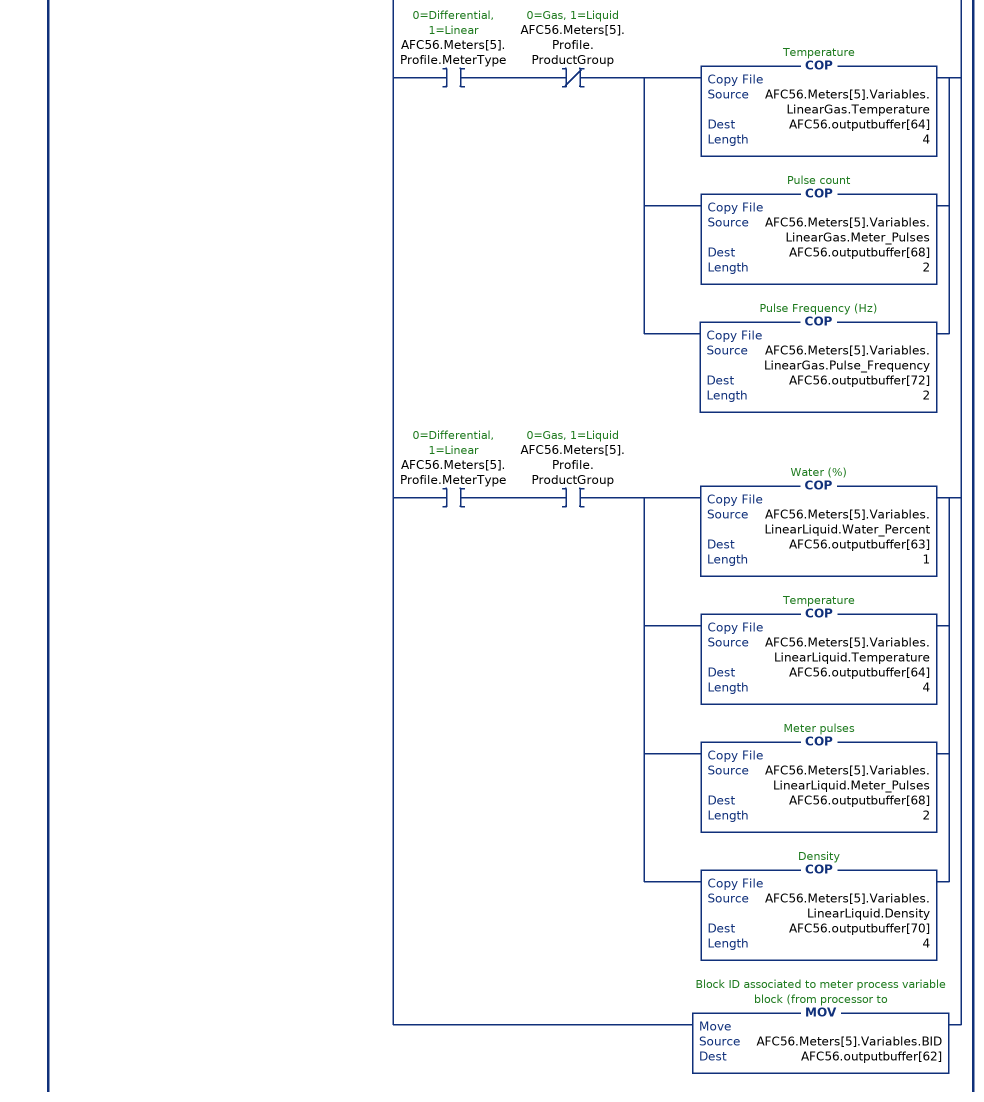
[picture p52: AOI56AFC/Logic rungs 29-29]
   29: XIO(AFC56.Flags.AFC_Set_Clock)LIM(1,AFC56.CycleCounter,16)[ADD(6,8192,AFC56.Meters[5].Variables.BID) ,XIO(AFC56.EnableStatus.Meter6) [OTE(AFC56.Meters[5].Variables.BID.8) ,OTU(AFC56.DisableMeter.Meter6) ] ,XIC(AFC56.EnableStatus.Meter6) OTU(AFC56.EnableMeter.Meter6) ,XIO(AFC56.Meters[5].Profile.MeterType) XIO(AFC56.Meters[5].Profile.ProductGroup) COP(AFC56.Meters[5].Variables.DifferentialGas.Temperature,AFC56.outputbuffer[64],6) ,XIO(AFC56.Meters[5].Profile.MeterType) XIC(AFC56.Meters[5].Profile.ProductGroup) [COP(AFC56.Meters[5].Variables.DifferentialLiquid.Water_Percent,AFC56.outputbuffer[63],1) ,COP(AFC56.Meters[5].Variables.DifferentialLiquid.Temperature,AFC56.outputbuffer[64],8) ] ,XIC(AFC56.Meters[5].Profile.MeterType) XIO(AFC56.Meters[5].Profile.ProductGroup) [COP(AFC56.Meters[5].Variables.LinearGas.Temperature,AFC56.outputbuffer[64],4) ,COP(AFC56.Meters[5].Variables.LinearGas.Meter_Pulses,AFC56.outputbuffer[68],2) ,COP(AFC56.Meters[5].Variables.LinearGas.Pulse_Frequency,AFC56.outputbuffer[72],2) ] ,XIC(AFC56.Meters[5].Profile.MeterType) XIC(AFC56.Meters[5].Profile.ProductGroup) [COP(AFC56.Meters[5].Variables.LinearLiquid.Water_Percent,AFC56.outputbuffer[63],1) ,COP(AFC56.Meters[5].Variables.LinearLiquid.Temperature,AFC56.outputbuffer[64],4) ,COP(AFC56.Meters[5].Variables.LinearLiquid.Meter_Pulses,AFC56.outputbuffer[68],2) ,COP(AFC56.Meters[5].Variables.LinearLiquid.Density,AFC56.outputbuffer[70],4) ] ,MOV(AFC56.Meters[5].Variables.BID,AFC56.outputbuffer[62]) ];
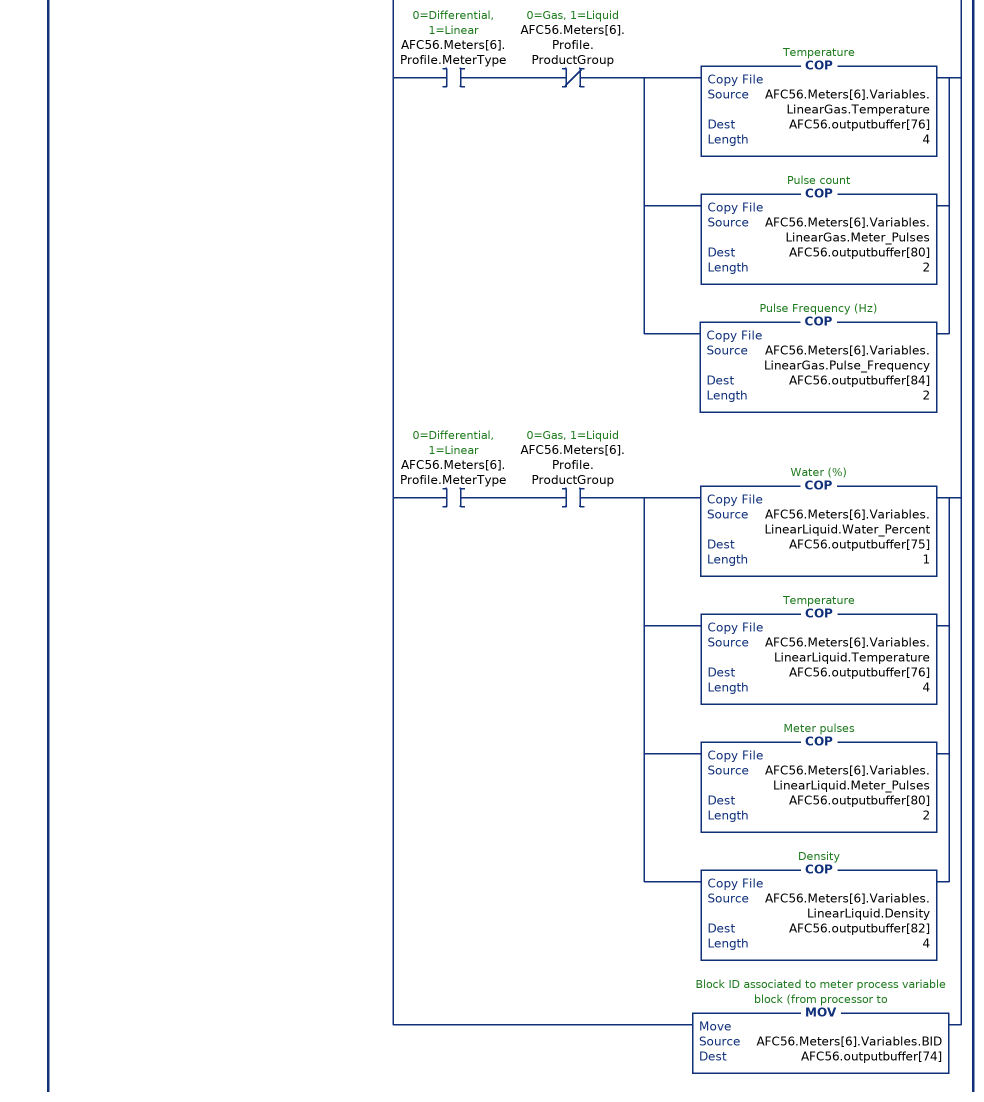
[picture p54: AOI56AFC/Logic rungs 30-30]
   30: XIO(AFC56.Flags.AFC_Set_Clock)LIM(1,AFC56.CycleCounter,16)[ADD(7,8192,AFC56.Meters[6].Variables.BID) ,XIO(AFC56.EnableStatus.Meter7) [OTE(AFC56.Meters[6].Variables.BID.8) ,OTU(AFC56.DisableMeter.Meter7) ] ,XIC(AFC56.EnableStatus.Meter7) OTU(AFC56.EnableMeter.Meter7) ,XIO(AFC56.Meters[6].Profile.MeterType) XIO(AFC56.Meters[6].Profile.ProductGroup) COP(AFC56.Meters[6].Variables.DifferentialGas.Temperature,AFC56.outputbuffer[76],6) ,XIO(AFC56.Meters[6].Profile.MeterType) XIC(AFC56.Meters[6].Profile.ProductGroup) [COP(AFC56.Meters[6].Variables.DifferentialLiquid.Water_Percent,AFC56.outputbuffer[75],1) ,COP(AFC56.Meters[6].Variables.DifferentialLiquid.Temperature,AFC56.outputbuffer[76],8) ] ,XIC(AFC56.Meters[6].Profile.MeterType) XIO(AFC56.Meters[6].Profile.ProductGroup) [COP(AFC56.Meters[6].Variables.LinearGas.Temperature,AFC56.outputbuffer[76],4) ,COP(AFC56.Meters[6].Variables.LinearGas.Meter_Pulses,AFC56.outputbuffer[80],2) ,COP(AFC56.Meters[6].Variables.LinearGas.Pulse_Frequency,AFC56.outputbuffer[84],2) ] ,XIC(AFC56.Meters[6].Profile.MeterType) XIC(AFC56.Meters[6].Profile.ProductGroup) [COP(AFC56.Meters[6].Variables.LinearLiquid.Water_Percent,AFC56.outputbuffer[75],1) ,COP(AFC56.Meters[6].Variables.LinearLiquid.Temperature,AFC56.outputbuffer[76],4) ,COP(AFC56.Meters[6].Variables.LinearLiquid.Meter_Pulses,AFC56.outputbuffer[80],2) ,COP(AFC56.Meters[6].Variables.LinearLiquid.Density,AFC56.outputbuffer[82],4) ] ,MOV(AFC56.Meters[6].Variables.BID,AFC56.outputbuffer[74]) ];
